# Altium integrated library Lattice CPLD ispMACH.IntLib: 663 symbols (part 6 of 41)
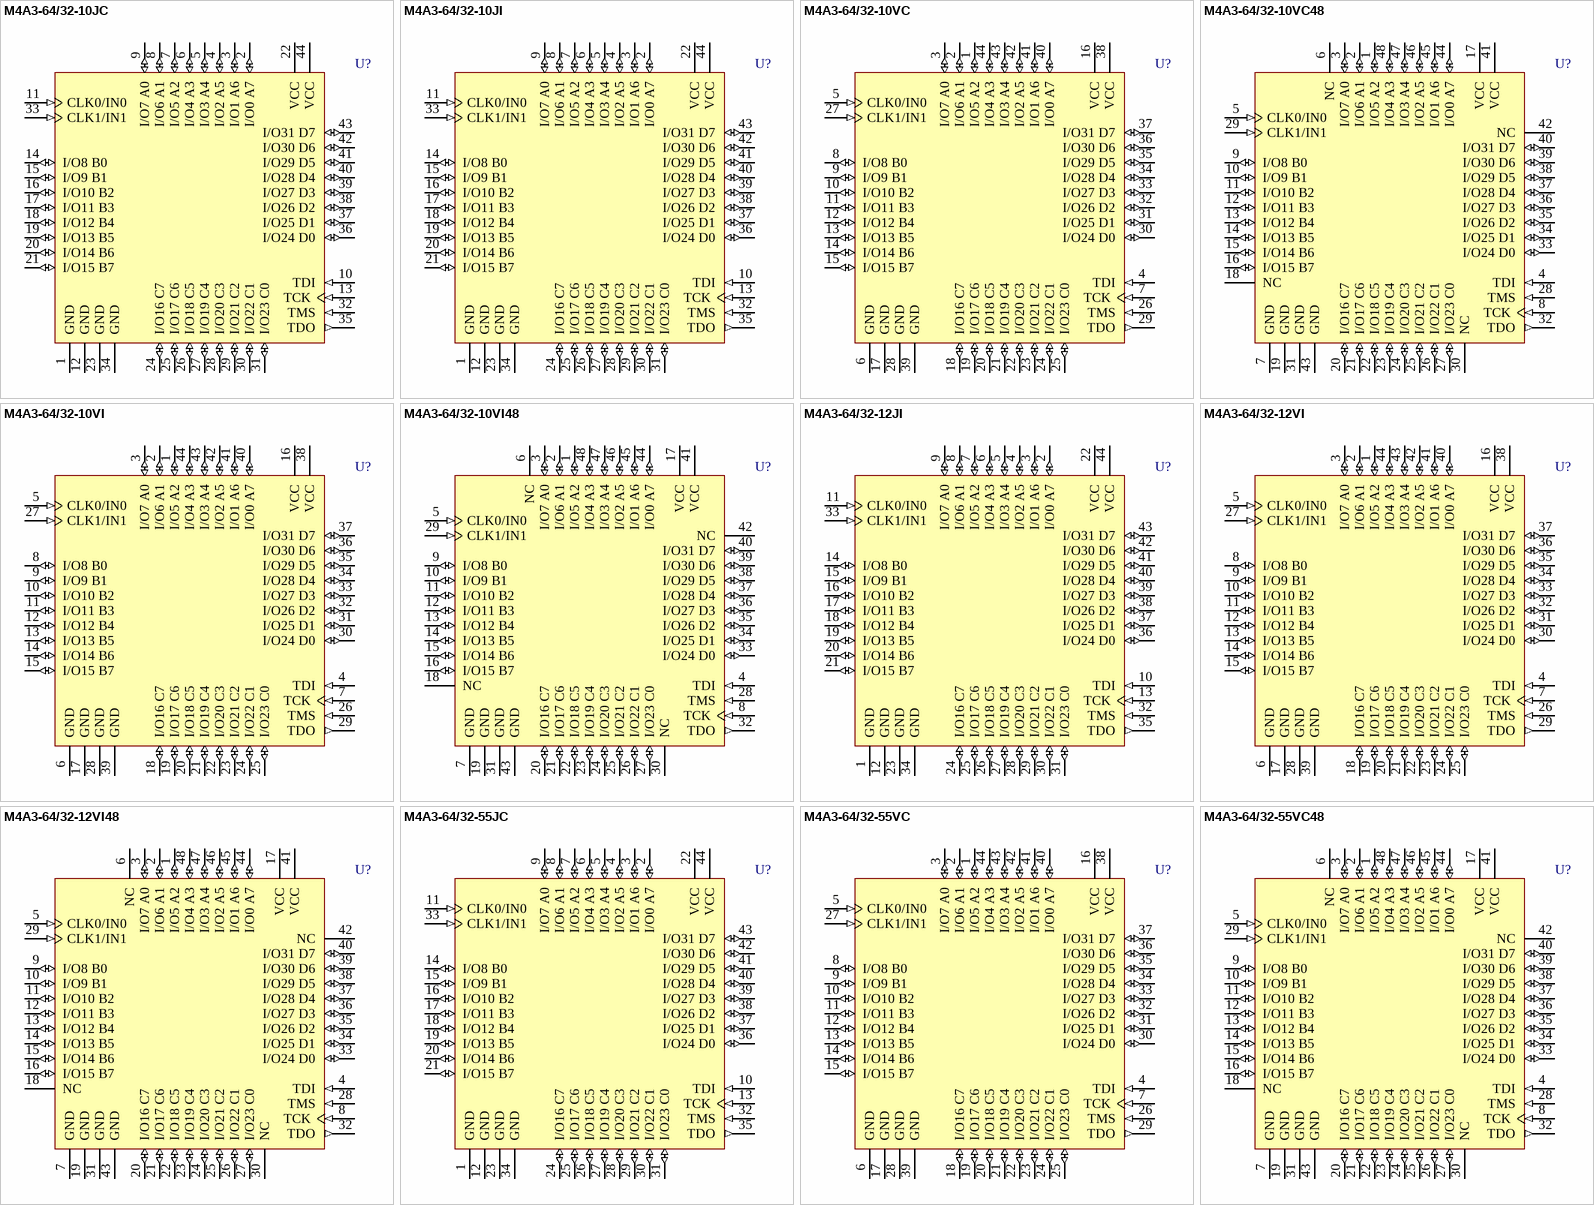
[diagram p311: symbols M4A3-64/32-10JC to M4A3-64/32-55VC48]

## M4A3-64/32-10JC
designator U?
High-Performance EE CMOS In-System Programmable Logic
footprint PLCC44_N (Leaded Chip Carrier, 44-Leads, Body 16.6x16.6mm, Pitch 1.27mm, IPC Medium Density)
footprint PLCC44_L (Leaded Chip Carrier, 44-Leads, Body 16.6x16.6mm, Pitch 1.27mm, IPC High Density)
footprint PLCC44_M (Leaded Chip Carrier, 44-Leads, Body 16.6x16.6mm, Pitch 1.27mm, IPC Low Density)
3D model M4A3-PLCC44 (44-Pin Leaded Chip Carrier 1.27 mm Pitch)
pins: 1 GND (power), 2 I/O0 A7 (io), 3 I/O1 A6 (io), 4 I/O2 A5 (io), 5 I/O3 A4 (io), 6 I/O4 A3 (io), 7 I/O5 A2 (io), 8 I/O6 A1 (io), 9 I/O7 A0 (io), 10 TDI (in), 11 CLK0/IN0 (in), 12 GND (power), 13 TCK (in), 14 I/O8 B0 (io), 15 I/O9 B1 (io), 16 I/O10 B2 (io), 17 I/O11 B3 (io), 18 I/O12 B4 (io), 19 I/O13 B5 (io), 20 I/O14 B6 (io), 21 I/O15 B7 (io), 22 VCC (power), 23 GND (power), 24 I/O16 C7 (io), 25 I/O17 C6 (io), 26 I/O18 C5 (io), 27 I/O19 C4 (io), 28 I/O20 C3 (io), 29 I/O21 C2 (io), 30 I/O22 C1 (io), 31 I/O23 C0 (io), 32 TMS (in), 33 CLK1/IN1 (in), 34 GND (power), 35 TDO (out), 36 I/O24 D0 (io), 37 I/O25 D1 (io), 38 I/O26 D2 (io), 39 I/O27 D3 (io), 40 I/O28 D4 (io), 41 I/O29 D5 (io), 42 I/O30 D6 (io), 43 I/O31 D7 (io), 44 VCC (power)

## M4A3-64/32-10JI
designator U?
High-Performance EE CMOS In-System Programmable Logic
footprint PLCC44_N (Leaded Chip Carrier, 44-Leads, Body 16.6x16.6mm, Pitch 1.27mm, IPC Medium Density)
footprint PLCC44_L (Leaded Chip Carrier, 44-Leads, Body 16.6x16.6mm, Pitch 1.27mm, IPC High Density)
footprint PLCC44_M (Leaded Chip Carrier, 44-Leads, Body 16.6x16.6mm, Pitch 1.27mm, IPC Low Density)
3D model M4A3-PLCC44 (44-Pin Leaded Chip Carrier 1.27 mm Pitch)
pins: 1 GND (power), 2 I/O0 A7 (io), 3 I/O1 A6 (io), 4 I/O2 A5 (io), 5 I/O3 A4 (io), 6 I/O4 A3 (io), 7 I/O5 A2 (io), 8 I/O6 A1 (io), 9 I/O7 A0 (io), 10 TDI (in), 11 CLK0/IN0 (in), 12 GND (power), 13 TCK (in), 14 I/O8 B0 (io), 15 I/O9 B1 (io), 16 I/O10 B2 (io), 17 I/O11 B3 (io), 18 I/O12 B4 (io), 19 I/O13 B5 (io), 20 I/O14 B6 (io), 21 I/O15 B7 (io), 22 VCC (power), 23 GND (power), 24 I/O16 C7 (io), 25 I/O17 C6 (io), 26 I/O18 C5 (io), 27 I/O19 C4 (io), 28 I/O20 C3 (io), 29 I/O21 C2 (io), 30 I/O22 C1 (io), 31 I/O23 C0 (io), 32 TMS (in), 33 CLK1/IN1 (in), 34 GND (power), 35 TDO (out), 36 I/O24 D0 (io), 37 I/O25 D1 (io), 38 I/O26 D2 (io), 39 I/O27 D3 (io), 40 I/O28 D4 (io), 41 I/O29 D5 (io), 42 I/O30 D6 (io), 43 I/O31 D7 (io), 44 VCC (power)

## M4A3-64/32-10VC
designator U?
High-Performance EE CMOS In-System Programmable Logic
footprint TQFP44_N (Thin QFP, 44-Leads, Body 10x10mm, Pitch 0.8mm, IPC Medium Density)
footprint TQFP44_L (Thin QFP, 44-Leads, Body 10x10mm, Pitch 0.8mm, IPC High Density)
footprint TQFP44_M (Thin QFP, 44-Leads, Body 10x10mm, Pitch 0.8mm, IPC Low Density)
3D model M4A3-TQFP44 (44-Pin Thin Quad Flat Pack 0.8 mm Pitch)
pins: 1 I/O5 A2 (io), 2 I/O6 A1 (io), 3 I/O7 A0 (io), 4 TDI (in), 5 CLK0/IN0 (in), 6 GND (power), 7 TCK (in), 8 I/O8 B0 (io), 9 I/O9 B1 (io), 10 I/O10 B2 (io), 11 I/O11 B3 (io), 12 I/O12 B4 (io), 13 I/O13 B5 (io), 14 I/O14 B6 (io), 15 I/O15 B7 (io), 16 VCC (power), 17 GND (power), 18 I/O16 C7 (io), 19 I/O17 C6 (io), 20 I/O18 C5 (io), 21 I/O19 C4 (io), 22 I/O20 C3 (io), 23 I/O21 C2 (io), 24 I/O22 C1 (io), 25 I/O23 C0 (io), 26 TMS (in), 27 CLK1/IN1 (in), 28 GND (power), 29 TDO (out), 30 I/O24 D0 (io), 31 I/O25 D1 (io), 32 I/O26 D2 (io), 33 I/O27 D3 (io), 34 I/O28 D4 (io), 35 I/O29 D5 (io), 36 I/O30 D6 (io), 37 I/O31 D7 (io), 38 VCC (power), 39 GND (power), 40 I/O0 A7 (io), 41 I/O1 A6 (io), 42 I/O2 A5 (io), 43 I/O3 A4 (io), 44 I/O4 A3 (io)

## M4A3-64/32-10VC48
designator U?
High-Performance EE CMOS In-System Programmable Logic
footprint TQFP48_N (Thin QFP, 48-Leads, Body 7x7mm, Pitch 0.5mm, IPC Medium Density)
footprint TQFP48_L (Thin QFP, 48-Leads, Body 7x7mm, Pitch 0.5mm, IPC High Density)
footprint TQFP48_M (Thin QFP, 48-Leads, Body 7x7mm, Pitch 0.5mm, IPC Low Density)
3D model M4A3-TQFP48 (48-Pin Thin Quad Flat Pack 0.5 mm Pitch)
pins: 1 I/O5 A2 (io), 2 I/O6 A1 (io), 3 I/O7 A0 (io), 4 TDI (in), 5 CLK0/IN0 (in), 6 NC, 7 GND (power), 8 TCK (in), 9 I/O8 B0 (io), 10 I/O9 B1 (io), 11 I/O10 B2 (io), 12 I/O11 B3 (io), 13 I/O12 B4 (io), 14 I/O13 B5 (io), 15 I/O14 B6 (io), 16 I/O15 B7 (io), 17 VCC (power), 18 NC, 19 GND (power), 20 I/O16 C7 (io), 21 I/O17 C6 (io), 22 I/O18 C5 (io), 23 I/O19 C4 (io), 24 I/O20 C3 (io), 25 I/O21 C2 (io), 26 I/O22 C1 (io), 27 I/O23 C0 (io), 28 TMS (in), 29 CLK1/IN1 (in), 30 NC, 31 GND (power), 32 TDO (out), 33 I/O24 D0 (io), 34 I/O25 D1 (io), 35 I/O26 D2 (io), 36 I/O27 D3 (io), 37 I/O28 D4 (io), 38 I/O29 D5 (io), 39 I/O30 D6 (io), 40 I/O31 D7 (io), 41 VCC (power), 42 NC, 43 GND (power), 44 I/O0 A7 (io), 45 I/O1 A6 (io), 46 I/O2 A5 (io), 47 I/O3 A4 (io), 48 I/O4 A3 (io)

## M4A3-64/32-10VI
designator U?
High-Performance EE CMOS In-System Programmable Logic
footprint TQFP44_N (Thin QFP, 44-Leads, Body 10x10mm, Pitch 0.8mm, IPC Medium Density)
footprint TQFP44_L (Thin QFP, 44-Leads, Body 10x10mm, Pitch 0.8mm, IPC High Density)
footprint TQFP44_M (Thin QFP, 44-Leads, Body 10x10mm, Pitch 0.8mm, IPC Low Density)
3D model M4A3-TQFP44 (44-Pin Thin Quad Flat Pack 0.8 mm Pitch)
pins: 1 I/O5 A2 (io), 2 I/O6 A1 (io), 3 I/O7 A0 (io), 4 TDI (in), 5 CLK0/IN0 (in), 6 GND (power), 7 TCK (in), 8 I/O8 B0 (io), 9 I/O9 B1 (io), 10 I/O10 B2 (io), 11 I/O11 B3 (io), 12 I/O12 B4 (io), 13 I/O13 B5 (io), 14 I/O14 B6 (io), 15 I/O15 B7 (io), 16 VCC (power), 17 GND (power), 18 I/O16 C7 (io), 19 I/O17 C6 (io), 20 I/O18 C5 (io), 21 I/O19 C4 (io), 22 I/O20 C3 (io), 23 I/O21 C2 (io), 24 I/O22 C1 (io), 25 I/O23 C0 (io), 26 TMS (in), 27 CLK1/IN1 (in), 28 GND (power), 29 TDO (out), 30 I/O24 D0 (io), 31 I/O25 D1 (io), 32 I/O26 D2 (io), 33 I/O27 D3 (io), 34 I/O28 D4 (io), 35 I/O29 D5 (io), 36 I/O30 D6 (io), 37 I/O31 D7 (io), 38 VCC (power), 39 GND (power), 40 I/O0 A7 (io), 41 I/O1 A6 (io), 42 I/O2 A5 (io), 43 I/O3 A4 (io), 44 I/O4 A3 (io)

## M4A3-64/32-10VI48
designator U?
High-Performance EE CMOS In-System Programmable Logic
footprint TQFP48_N (Thin QFP, 48-Leads, Body 7x7mm, Pitch 0.5mm, IPC Medium Density)
footprint TQFP48_L (Thin QFP, 48-Leads, Body 7x7mm, Pitch 0.5mm, IPC High Density)
footprint TQFP48_M (Thin QFP, 48-Leads, Body 7x7mm, Pitch 0.5mm, IPC Low Density)
3D model M4A3-TQFP48 (48-Pin Thin Quad Flat Pack 0.5 mm Pitch)
pins: 1 I/O5 A2 (io), 2 I/O6 A1 (io), 3 I/O7 A0 (io), 4 TDI (in), 5 CLK0/IN0 (in), 6 NC, 7 GND (power), 8 TCK (in), 9 I/O8 B0 (io), 10 I/O9 B1 (io), 11 I/O10 B2 (io), 12 I/O11 B3 (io), 13 I/O12 B4 (io), 14 I/O13 B5 (io), 15 I/O14 B6 (io), 16 I/O15 B7 (io), 17 VCC (power), 18 NC, 19 GND (power), 20 I/O16 C7 (io), 21 I/O17 C6 (io), 22 I/O18 C5 (io), 23 I/O19 C4 (io), 24 I/O20 C3 (io), 25 I/O21 C2 (io), 26 I/O22 C1 (io), 27 I/O23 C0 (io), 28 TMS (in), 29 CLK1/IN1 (in), 30 NC, 31 GND (power), 32 TDO (out), 33 I/O24 D0 (io), 34 I/O25 D1 (io), 35 I/O26 D2 (io), 36 I/O27 D3 (io), 37 I/O28 D4 (io), 38 I/O29 D5 (io), 39 I/O30 D6 (io), 40 I/O31 D7 (io), 41 VCC (power), 42 NC, 43 GND (power), 44 I/O0 A7 (io), 45 I/O1 A6 (io), 46 I/O2 A5 (io), 47 I/O3 A4 (io), 48 I/O4 A3 (io)

## M4A3-64/32-12JI
designator U?
High-Performance EE CMOS In-System Programmable Logic
footprint PLCC44_N (Leaded Chip Carrier, 44-Leads, Body 16.6x16.6mm, Pitch 1.27mm, IPC Medium Density)
footprint PLCC44_L (Leaded Chip Carrier, 44-Leads, Body 16.6x16.6mm, Pitch 1.27mm, IPC High Density)
footprint PLCC44_M (Leaded Chip Carrier, 44-Leads, Body 16.6x16.6mm, Pitch 1.27mm, IPC Low Density)
3D model M4A3-PLCC44 (44-Pin Leaded Chip Carrier 1.27 mm Pitch)
pins: 1 GND (power), 2 I/O0 A7 (io), 3 I/O1 A6 (io), 4 I/O2 A5 (io), 5 I/O3 A4 (io), 6 I/O4 A3 (io), 7 I/O5 A2 (io), 8 I/O6 A1 (io), 9 I/O7 A0 (io), 10 TDI (in), 11 CLK0/IN0 (in), 12 GND (power), 13 TCK (in), 14 I/O8 B0 (io), 15 I/O9 B1 (io), 16 I/O10 B2 (io), 17 I/O11 B3 (io), 18 I/O12 B4 (io), 19 I/O13 B5 (io), 20 I/O14 B6 (io), 21 I/O15 B7 (io), 22 VCC (power), 23 GND (power), 24 I/O16 C7 (io), 25 I/O17 C6 (io), 26 I/O18 C5 (io), 27 I/O19 C4 (io), 28 I/O20 C3 (io), 29 I/O21 C2 (io), 30 I/O22 C1 (io), 31 I/O23 C0 (io), 32 TMS (in), 33 CLK1/IN1 (in), 34 GND (power), 35 TDO (out), 36 I/O24 D0 (io), 37 I/O25 D1 (io), 38 I/O26 D2 (io), 39 I/O27 D3 (io), 40 I/O28 D4 (io), 41 I/O29 D5 (io), 42 I/O30 D6 (io), 43 I/O31 D7 (io), 44 VCC (power)

## M4A3-64/32-12VI
designator U?
High-Performance EE CMOS In-System Programmable Logic
footprint TQFP44_N (Thin QFP, 44-Leads, Body 10x10mm, Pitch 0.8mm, IPC Medium Density)
footprint TQFP44_L (Thin QFP, 44-Leads, Body 10x10mm, Pitch 0.8mm, IPC High Density)
footprint TQFP44_M (Thin QFP, 44-Leads, Body 10x10mm, Pitch 0.8mm, IPC Low Density)
3D model M4A3-TQFP44 (44-Pin Thin Quad Flat Pack 0.8 mm Pitch)
pins: 1 I/O5 A2 (io), 2 I/O6 A1 (io), 3 I/O7 A0 (io), 4 TDI (in), 5 CLK0/IN0 (in), 6 GND (power), 7 TCK (in), 8 I/O8 B0 (io), 9 I/O9 B1 (io), 10 I/O10 B2 (io), 11 I/O11 B3 (io), 12 I/O12 B4 (io), 13 I/O13 B5 (io), 14 I/O14 B6 (io), 15 I/O15 B7 (io), 16 VCC (power), 17 GND (power), 18 I/O16 C7 (io), 19 I/O17 C6 (io), 20 I/O18 C5 (io), 21 I/O19 C4 (io), 22 I/O20 C3 (io), 23 I/O21 C2 (io), 24 I/O22 C1 (io), 25 I/O23 C0 (io), 26 TMS (in), 27 CLK1/IN1 (in), 28 GND (power), 29 TDO (out), 30 I/O24 D0 (io), 31 I/O25 D1 (io), 32 I/O26 D2 (io), 33 I/O27 D3 (io), 34 I/O28 D4 (io), 35 I/O29 D5 (io), 36 I/O30 D6 (io), 37 I/O31 D7 (io), 38 VCC (power), 39 GND (power), 40 I/O0 A7 (io), 41 I/O1 A6 (io), 42 I/O2 A5 (io), 43 I/O3 A4 (io), 44 I/O4 A3 (io)

## M4A3-64/32-12VI48
designator U?
High-Performance EE CMOS In-System Programmable Logic
footprint TQFP48_N (Thin QFP, 48-Leads, Body 7x7mm, Pitch 0.5mm, IPC Medium Density)
footprint TQFP48_L (Thin QFP, 48-Leads, Body 7x7mm, Pitch 0.5mm, IPC High Density)
footprint TQFP48_M (Thin QFP, 48-Leads, Body 7x7mm, Pitch 0.5mm, IPC Low Density)
3D model M4A3-TQFP48 (48-Pin Thin Quad Flat Pack 0.5 mm Pitch)
pins: 1 I/O5 A2 (io), 2 I/O6 A1 (io), 3 I/O7 A0 (io), 4 TDI (in), 5 CLK0/IN0 (in), 6 NC, 7 GND (power), 8 TCK (in), 9 I/O8 B0 (io), 10 I/O9 B1 (io), 11 I/O10 B2 (io), 12 I/O11 B3 (io), 13 I/O12 B4 (io), 14 I/O13 B5 (io), 15 I/O14 B6 (io), 16 I/O15 B7 (io), 17 VCC (power), 18 NC, 19 GND (power), 20 I/O16 C7 (io), 21 I/O17 C6 (io), 22 I/O18 C5 (io), 23 I/O19 C4 (io), 24 I/O20 C3 (io), 25 I/O21 C2 (io), 26 I/O22 C1 (io), 27 I/O23 C0 (io), 28 TMS (in), 29 CLK1/IN1 (in), 30 NC, 31 GND (power), 32 TDO (out), 33 I/O24 D0 (io), 34 I/O25 D1 (io), 35 I/O26 D2 (io), 36 I/O27 D3 (io), 37 I/O28 D4 (io), 38 I/O29 D5 (io), 39 I/O30 D6 (io), 40 I/O31 D7 (io), 41 VCC (power), 42 NC, 43 GND (power), 44 I/O0 A7 (io), 45 I/O1 A6 (io), 46 I/O2 A5 (io), 47 I/O3 A4 (io), 48 I/O4 A3 (io)

## M4A3-64/32-55JC
designator U?
High-Performance EE CMOS In-System Programmable Logic
footprint PLCC44_N (Leaded Chip Carrier, 44-Leads, Body 16.6x16.6mm, Pitch 1.27mm, IPC Medium Density)
footprint PLCC44_L (Leaded Chip Carrier, 44-Leads, Body 16.6x16.6mm, Pitch 1.27mm, IPC High Density)
footprint PLCC44_M (Leaded Chip Carrier, 44-Leads, Body 16.6x16.6mm, Pitch 1.27mm, IPC Low Density)
3D model M4A3-PLCC44 (44-Pin Leaded Chip Carrier 1.27 mm Pitch)
pins: 1 GND (power), 2 I/O0 A7 (io), 3 I/O1 A6 (io), 4 I/O2 A5 (io), 5 I/O3 A4 (io), 6 I/O4 A3 (io), 7 I/O5 A2 (io), 8 I/O6 A1 (io), 9 I/O7 A0 (io), 10 TDI (in), 11 CLK0/IN0 (in), 12 GND (power), 13 TCK (in), 14 I/O8 B0 (io), 15 I/O9 B1 (io), 16 I/O10 B2 (io), 17 I/O11 B3 (io), 18 I/O12 B4 (io), 19 I/O13 B5 (io), 20 I/O14 B6 (io), 21 I/O15 B7 (io), 22 VCC (power), 23 GND (power), 24 I/O16 C7 (io), 25 I/O17 C6 (io), 26 I/O18 C5 (io), 27 I/O19 C4 (io), 28 I/O20 C3 (io), 29 I/O21 C2 (io), 30 I/O22 C1 (io), 31 I/O23 C0 (io), 32 TMS (in), 33 CLK1/IN1 (in), 34 GND (power), 35 TDO (out), 36 I/O24 D0 (io), 37 I/O25 D1 (io), 38 I/O26 D2 (io), 39 I/O27 D3 (io), 40 I/O28 D4 (io), 41 I/O29 D5 (io), 42 I/O30 D6 (io), 43 I/O31 D7 (io), 44 VCC (power)

## M4A3-64/32-55VC
designator U?
High-Performance EE CMOS In-System Programmable Logic
footprint TQFP44_N (Thin QFP, 44-Leads, Body 10x10mm, Pitch 0.8mm, IPC Medium Density)
footprint TQFP44_L (Thin QFP, 44-Leads, Body 10x10mm, Pitch 0.8mm, IPC High Density)
footprint TQFP44_M (Thin QFP, 44-Leads, Body 10x10mm, Pitch 0.8mm, IPC Low Density)
3D model M4A3-TQFP44 (44-Pin Thin Quad Flat Pack 0.8 mm Pitch)
pins: 1 I/O5 A2 (io), 2 I/O6 A1 (io), 3 I/O7 A0 (io), 4 TDI (in), 5 CLK0/IN0 (in), 6 GND (power), 7 TCK (in), 8 I/O8 B0 (io), 9 I/O9 B1 (io), 10 I/O10 B2 (io), 11 I/O11 B3 (io), 12 I/O12 B4 (io), 13 I/O13 B5 (io), 14 I/O14 B6 (io), 15 I/O15 B7 (io), 16 VCC (power), 17 GND (power), 18 I/O16 C7 (io), 19 I/O17 C6 (io), 20 I/O18 C5 (io), 21 I/O19 C4 (io), 22 I/O20 C3 (io), 23 I/O21 C2 (io), 24 I/O22 C1 (io), 25 I/O23 C0 (io), 26 TMS (in), 27 CLK1/IN1 (in), 28 GND (power), 29 TDO (out), 30 I/O24 D0 (io), 31 I/O25 D1 (io), 32 I/O26 D2 (io), 33 I/O27 D3 (io), 34 I/O28 D4 (io), 35 I/O29 D5 (io), 36 I/O30 D6 (io), 37 I/O31 D7 (io), 38 VCC (power), 39 GND (power), 40 I/O0 A7 (io), 41 I/O1 A6 (io), 42 I/O2 A5 (io), 43 I/O3 A4 (io), 44 I/O4 A3 (io)

## M4A3-64/32-55VC48
designator U?
High-Performance EE CMOS In-System Programmable Logic
footprint TQFP48_N (Thin QFP, 48-Leads, Body 7x7mm, Pitch 0.5mm, IPC Medium Density)
footprint TQFP48_L (Thin QFP, 48-Leads, Body 7x7mm, Pitch 0.5mm, IPC High Density)
footprint TQFP48_M (Thin QFP, 48-Leads, Body 7x7mm, Pitch 0.5mm, IPC Low Density)
3D model M4A3-TQFP48 (48-Pin Thin Quad Flat Pack 0.5 mm Pitch)
pins: 1 I/O5 A2 (io), 2 I/O6 A1 (io), 3 I/O7 A0 (io), 4 TDI (in), 5 CLK0/IN0 (in), 6 NC, 7 GND (power), 8 TCK (in), 9 I/O8 B0 (io), 10 I/O9 B1 (io), 11 I/O10 B2 (io), 12 I/O11 B3 (io), 13 I/O12 B4 (io), 14 I/O13 B5 (io), 15 I/O14 B6 (io), 16 I/O15 B7 (io), 17 VCC (power), 18 NC, 19 GND (power), 20 I/O16 C7 (io), 21 I/O17 C6 (io), 22 I/O18 C5 (io), 23 I/O19 C4 (io), 24 I/O20 C3 (io), 25 I/O21 C2 (io), 26 I/O22 C1 (io), 27 I/O23 C0 (io), 28 TMS (in), 29 CLK1/IN1 (in), 30 NC, 31 GND (power), 32 TDO (out), 33 I/O24 D0 (io), 34 I/O25 D1 (io), 35 I/O26 D2 (io), 36 I/O27 D3 (io), 37 I/O28 D4 (io), 38 I/O29 D5 (io), 39 I/O30 D6 (io), 40 I/O31 D7 (io), 41 VCC (power), 42 NC, 43 GND (power), 44 I/O0 A7 (io), 45 I/O1 A6 (io), 46 I/O2 A5 (io), 47 I/O3 A4 (io), 48 I/O4 A3 (io)

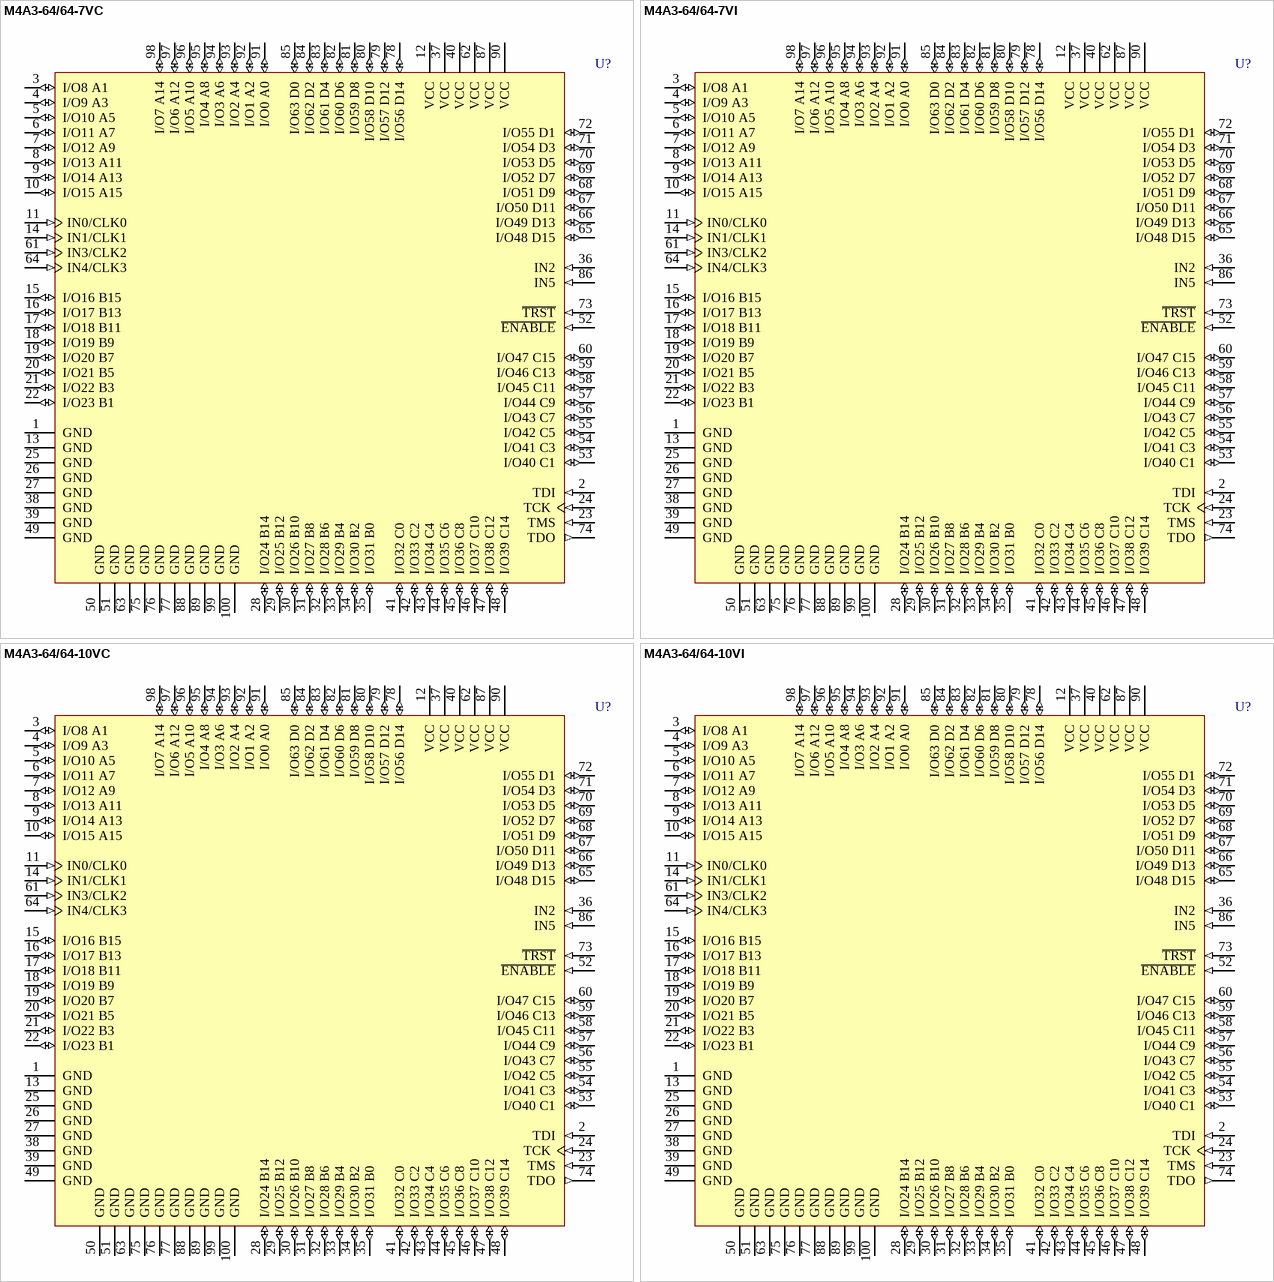
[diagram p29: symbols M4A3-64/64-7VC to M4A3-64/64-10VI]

## M4A3-64/64-7VC
designator U?
High-Performance EE CMOS In-System Programmable Logic
footprint TQFP100_N (Thin QFP, 100-Leads, Body 14x14mm, Pitch 0.5mm, IPC Medium Density)
footprint TQFP100_L (Thin QFP, 100-Leads, Body 14x14mm, Pitch 0.5mm, IPC High Density)
footprint TQFP100_M (Thin QFP, 100-Leads, Body 14x14mm, Pitch 0.5mm, IPC Low Density)
3D model M4A3-TQFP100 (100-Pin Thin Quad Flat Pack (TQFP100))
pins: 1 GND (power), 2 TDI (in), 3 I/O8 A1 (io), 4 I/O9 A3 (io), 5 I/O10 A5 (io), 6 I/O11 A7 (io), 7 I/O12 A9 (io), 8 I/O13 A11 (io), 9 I/O14 A13 (io), 10 I/O15 A15 (io), 11 IN0/CLK0 (in), 12 VCC (power), 13 GND (power), 14 IN1/CLK1 (in), 15 I/O16 B15 (io), 16 I/O17 B13 (io), 17 I/O18 B11 (io), 18 I/O19 B9 (io), 19 I/O20 B7 (io), 20 I/O21 B5 (io), 21 I/O22 B3 (io), 22 I/O23 B1 (io), 23 TMS (in), 24 TCK (in), 25 GND (power), 26 GND (power), 27 GND (power), 28 I/O24 B14 (io), 29 I/O25 B12 (io), 30 I/O26 B10 (io), 31 I/O27 B8 (io), 32 I/O28 B6 (io), 33 I/O29 B4 (io), 34 I/O30 B2 (io), 35 I/O31 B0 (io), 36 IN2 (in), 37 VCC (power), 38 GND (power), 39 GND (power), 40 VCC (power), 41 I/O32 C0 (io), 42 I/O33 C2 (io), 43 I/O34 C4 (io), 44 I/O35 C6 (io), 45 I/O36 C8 (io), 46 I/O37 C10 (io), 47 I/O38 C12 (io), 48 I/O39 C14 (io), 49 GND (power), 50 GND (power), 51 GND (power), 52 ~{ENABLE} (in), 53 I/O40 C1 (io), 54 I/O41 C3 (io), 55 I/O42 C5 (io), 56 I/O43 C7 (io), 57 I/O44 C9 (io), 58 I/O45 C11 (io), 59 I/O46 C13 (io), 60 I/O47 C15 (io), 61 IN3/CLK2 (in), 62 VCC (power), 63 GND (power), 64 IN4/CLK3 (in), 65 I/O48 D15 (io), 66 I/O49 D13 (io), 67 I/O50 D11 (io), 68 I/O51 D9 (io), 69 I/O52 D7 (io), 70 I/O53 D5 (io), 71 I/O54 D3 (io), 72 I/O55 D1 (io), 73 ~{TRST} (in), 74 TDO (out), 75 GND (power), 76 GND (power), 77 GND (power), 78 I/O56 D14 (io), 79 I/O57 D12 (io), 80 I/O58 D10 (io), 81 I/O59 D8 (io), 82 I/O60 D6 (io), 83 I/O61 D4 (io), 84 I/O62 D2 (io), 85 I/O63 D0 (io), 86 IN5 (in), 87 VCC (power), 88 GND (power), 89 GND (power), 90 VCC (power), 91 I/O0 A0 (io), 92 I/O1 A2 (io), 93 I/O2 A4 (io), 94 I/O3 A6 (io), 95 I/O4 A8 (io), 96 I/O5 A10 (io), 97 I/O6 A12 (io), 98 I/O7 A14 (io), 99 GND (power), 100 GND (power)

## M4A3-64/64-7VI
designator U?
High-Performance EE CMOS In-System Programmable Logic
footprint TQFP100_N (Thin QFP, 100-Leads, Body 14x14mm, Pitch 0.5mm, IPC Medium Density)
footprint TQFP100_L (Thin QFP, 100-Leads, Body 14x14mm, Pitch 0.5mm, IPC High Density)
footprint TQFP100_M (Thin QFP, 100-Leads, Body 14x14mm, Pitch 0.5mm, IPC Low Density)
3D model M4A3-TQFP100 (100-Pin Thin Quad Flat Pack (TQFP100))
pins: 1 GND (power), 2 TDI (in), 3 I/O8 A1 (io), 4 I/O9 A3 (io), 5 I/O10 A5 (io), 6 I/O11 A7 (io), 7 I/O12 A9 (io), 8 I/O13 A11 (io), 9 I/O14 A13 (io), 10 I/O15 A15 (io), 11 IN0/CLK0 (in), 12 VCC (power), 13 GND (power), 14 IN1/CLK1 (in), 15 I/O16 B15 (io), 16 I/O17 B13 (io), 17 I/O18 B11 (io), 18 I/O19 B9 (io), 19 I/O20 B7 (io), 20 I/O21 B5 (io), 21 I/O22 B3 (io), 22 I/O23 B1 (io), 23 TMS (in), 24 TCK (in), 25 GND (power), 26 GND (power), 27 GND (power), 28 I/O24 B14 (io), 29 I/O25 B12 (io), 30 I/O26 B10 (io), 31 I/O27 B8 (io), 32 I/O28 B6 (io), 33 I/O29 B4 (io), 34 I/O30 B2 (io), 35 I/O31 B0 (io), 36 IN2 (in), 37 VCC (power), 38 GND (power), 39 GND (power), 40 VCC (power), 41 I/O32 C0 (io), 42 I/O33 C2 (io), 43 I/O34 C4 (io), 44 I/O35 C6 (io), 45 I/O36 C8 (io), 46 I/O37 C10 (io), 47 I/O38 C12 (io), 48 I/O39 C14 (io), 49 GND (power), 50 GND (power), 51 GND (power), 52 ~{ENABLE} (in), 53 I/O40 C1 (io), 54 I/O41 C3 (io), 55 I/O42 C5 (io), 56 I/O43 C7 (io), 57 I/O44 C9 (io), 58 I/O45 C11 (io), 59 I/O46 C13 (io), 60 I/O47 C15 (io), 61 IN3/CLK2 (in), 62 VCC (power), 63 GND (power), 64 IN4/CLK3 (in), 65 I/O48 D15 (io), 66 I/O49 D13 (io), 67 I/O50 D11 (io), 68 I/O51 D9 (io), 69 I/O52 D7 (io), 70 I/O53 D5 (io), 71 I/O54 D3 (io), 72 I/O55 D1 (io), 73 ~{TRST} (in), 74 TDO (out), 75 GND (power), 76 GND (power), 77 GND (power), 78 I/O56 D14 (io), 79 I/O57 D12 (io), 80 I/O58 D10 (io), 81 I/O59 D8 (io), 82 I/O60 D6 (io), 83 I/O61 D4 (io), 84 I/O62 D2 (io), 85 I/O63 D0 (io), 86 IN5 (in), 87 VCC (power), 88 GND (power), 89 GND (power), 90 VCC (power), 91 I/O0 A0 (io), 92 I/O1 A2 (io), 93 I/O2 A4 (io), 94 I/O3 A6 (io), 95 I/O4 A8 (io), 96 I/O5 A10 (io), 97 I/O6 A12 (io), 98 I/O7 A14 (io), 99 GND (power), 100 GND (power)

## M4A3-64/64-10VC
designator U?
High-Performance EE CMOS In-System Programmable Logic
footprint TQFP100_N (Thin QFP, 100-Leads, Body 14x14mm, Pitch 0.5mm, IPC Medium Density)
footprint TQFP100_L (Thin QFP, 100-Leads, Body 14x14mm, Pitch 0.5mm, IPC High Density)
footprint TQFP100_M (Thin QFP, 100-Leads, Body 14x14mm, Pitch 0.5mm, IPC Low Density)
3D model M4A3-TQFP100 (100-Pin Thin Quad Flat Pack (TQFP100))
pins: 1 GND (power), 2 TDI (in), 3 I/O8 A1 (io), 4 I/O9 A3 (io), 5 I/O10 A5 (io), 6 I/O11 A7 (io), 7 I/O12 A9 (io), 8 I/O13 A11 (io), 9 I/O14 A13 (io), 10 I/O15 A15 (io), 11 IN0/CLK0 (in), 12 VCC (power), 13 GND (power), 14 IN1/CLK1 (in), 15 I/O16 B15 (io), 16 I/O17 B13 (io), 17 I/O18 B11 (io), 18 I/O19 B9 (io), 19 I/O20 B7 (io), 20 I/O21 B5 (io), 21 I/O22 B3 (io), 22 I/O23 B1 (io), 23 TMS (in), 24 TCK (in), 25 GND (power), 26 GND (power), 27 GND (power), 28 I/O24 B14 (io), 29 I/O25 B12 (io), 30 I/O26 B10 (io), 31 I/O27 B8 (io), 32 I/O28 B6 (io), 33 I/O29 B4 (io), 34 I/O30 B2 (io), 35 I/O31 B0 (io), 36 IN2 (in), 37 VCC (power), 38 GND (power), 39 GND (power), 40 VCC (power), 41 I/O32 C0 (io), 42 I/O33 C2 (io), 43 I/O34 C4 (io), 44 I/O35 C6 (io), 45 I/O36 C8 (io), 46 I/O37 C10 (io), 47 I/O38 C12 (io), 48 I/O39 C14 (io), 49 GND (power), 50 GND (power), 51 GND (power), 52 ~{ENABLE} (in), 53 I/O40 C1 (io), 54 I/O41 C3 (io), 55 I/O42 C5 (io), 56 I/O43 C7 (io), 57 I/O44 C9 (io), 58 I/O45 C11 (io), 59 I/O46 C13 (io), 60 I/O47 C15 (io), 61 IN3/CLK2 (in), 62 VCC (power), 63 GND (power), 64 IN4/CLK3 (in), 65 I/O48 D15 (io), 66 I/O49 D13 (io), 67 I/O50 D11 (io), 68 I/O51 D9 (io), 69 I/O52 D7 (io), 70 I/O53 D5 (io), 71 I/O54 D3 (io), 72 I/O55 D1 (io), 73 ~{TRST} (in), 74 TDO (out), 75 GND (power), 76 GND (power), 77 GND (power), 78 I/O56 D14 (io), 79 I/O57 D12 (io), 80 I/O58 D10 (io), 81 I/O59 D8 (io), 82 I/O60 D6 (io), 83 I/O61 D4 (io), 84 I/O62 D2 (io), 85 I/O63 D0 (io), 86 IN5 (in), 87 VCC (power), 88 GND (power), 89 GND (power), 90 VCC (power), 91 I/O0 A0 (io), 92 I/O1 A2 (io), 93 I/O2 A4 (io), 94 I/O3 A6 (io), 95 I/O4 A8 (io), 96 I/O5 A10 (io), 97 I/O6 A12 (io), 98 I/O7 A14 (io), 99 GND (power), 100 GND (power)

## M4A3-64/64-10VI
designator U?
High-Performance EE CMOS In-System Programmable Logic
footprint TQFP100_N (Thin QFP, 100-Leads, Body 14x14mm, Pitch 0.5mm, IPC Medium Density)
footprint TQFP100_L (Thin QFP, 100-Leads, Body 14x14mm, Pitch 0.5mm, IPC High Density)
footprint TQFP100_M (Thin QFP, 100-Leads, Body 14x14mm, Pitch 0.5mm, IPC Low Density)
3D model M4A3-TQFP100 (100-Pin Thin Quad Flat Pack (TQFP100))
pins: 1 GND (power), 2 TDI (in), 3 I/O8 A1 (io), 4 I/O9 A3 (io), 5 I/O10 A5 (io), 6 I/O11 A7 (io), 7 I/O12 A9 (io), 8 I/O13 A11 (io), 9 I/O14 A13 (io), 10 I/O15 A15 (io), 11 IN0/CLK0 (in), 12 VCC (power), 13 GND (power), 14 IN1/CLK1 (in), 15 I/O16 B15 (io), 16 I/O17 B13 (io), 17 I/O18 B11 (io), 18 I/O19 B9 (io), 19 I/O20 B7 (io), 20 I/O21 B5 (io), 21 I/O22 B3 (io), 22 I/O23 B1 (io), 23 TMS (in), 24 TCK (in), 25 GND (power), 26 GND (power), 27 GND (power), 28 I/O24 B14 (io), 29 I/O25 B12 (io), 30 I/O26 B10 (io), 31 I/O27 B8 (io), 32 I/O28 B6 (io), 33 I/O29 B4 (io), 34 I/O30 B2 (io), 35 I/O31 B0 (io), 36 IN2 (in), 37 VCC (power), 38 GND (power), 39 GND (power), 40 VCC (power), 41 I/O32 C0 (io), 42 I/O33 C2 (io), 43 I/O34 C4 (io), 44 I/O35 C6 (io), 45 I/O36 C8 (io), 46 I/O37 C10 (io), 47 I/O38 C12 (io), 48 I/O39 C14 (io), 49 GND (power), 50 GND (power), 51 GND (power), 52 ~{ENABLE} (in), 53 I/O40 C1 (io), 54 I/O41 C3 (io), 55 I/O42 C5 (io), 56 I/O43 C7 (io), 57 I/O44 C9 (io), 58 I/O45 C11 (io), 59 I/O46 C13 (io), 60 I/O47 C15 (io), 61 IN3/CLK2 (in), 62 VCC (power), 63 GND (power), 64 IN4/CLK3 (in), 65 I/O48 D15 (io), 66 I/O49 D13 (io), 67 I/O50 D11 (io), 68 I/O51 D9 (io), 69 I/O52 D7 (io), 70 I/O53 D5 (io), 71 I/O54 D3 (io), 72 I/O55 D1 (io), 73 ~{TRST} (in), 74 TDO (out), 75 GND (power), 76 GND (power), 77 GND (power), 78 I/O56 D14 (io), 79 I/O57 D12 (io), 80 I/O58 D10 (io), 81 I/O59 D8 (io), 82 I/O60 D6 (io), 83 I/O61 D4 (io), 84 I/O62 D2 (io), 85 I/O63 D0 (io), 86 IN5 (in), 87 VCC (power), 88 GND (power), 89 GND (power), 90 VCC (power), 91 I/O0 A0 (io), 92 I/O1 A2 (io), 93 I/O2 A4 (io), 94 I/O3 A6 (io), 95 I/O4 A8 (io), 96 I/O5 A10 (io), 97 I/O6 A12 (io), 98 I/O7 A14 (io), 99 GND (power), 100 GND (power)

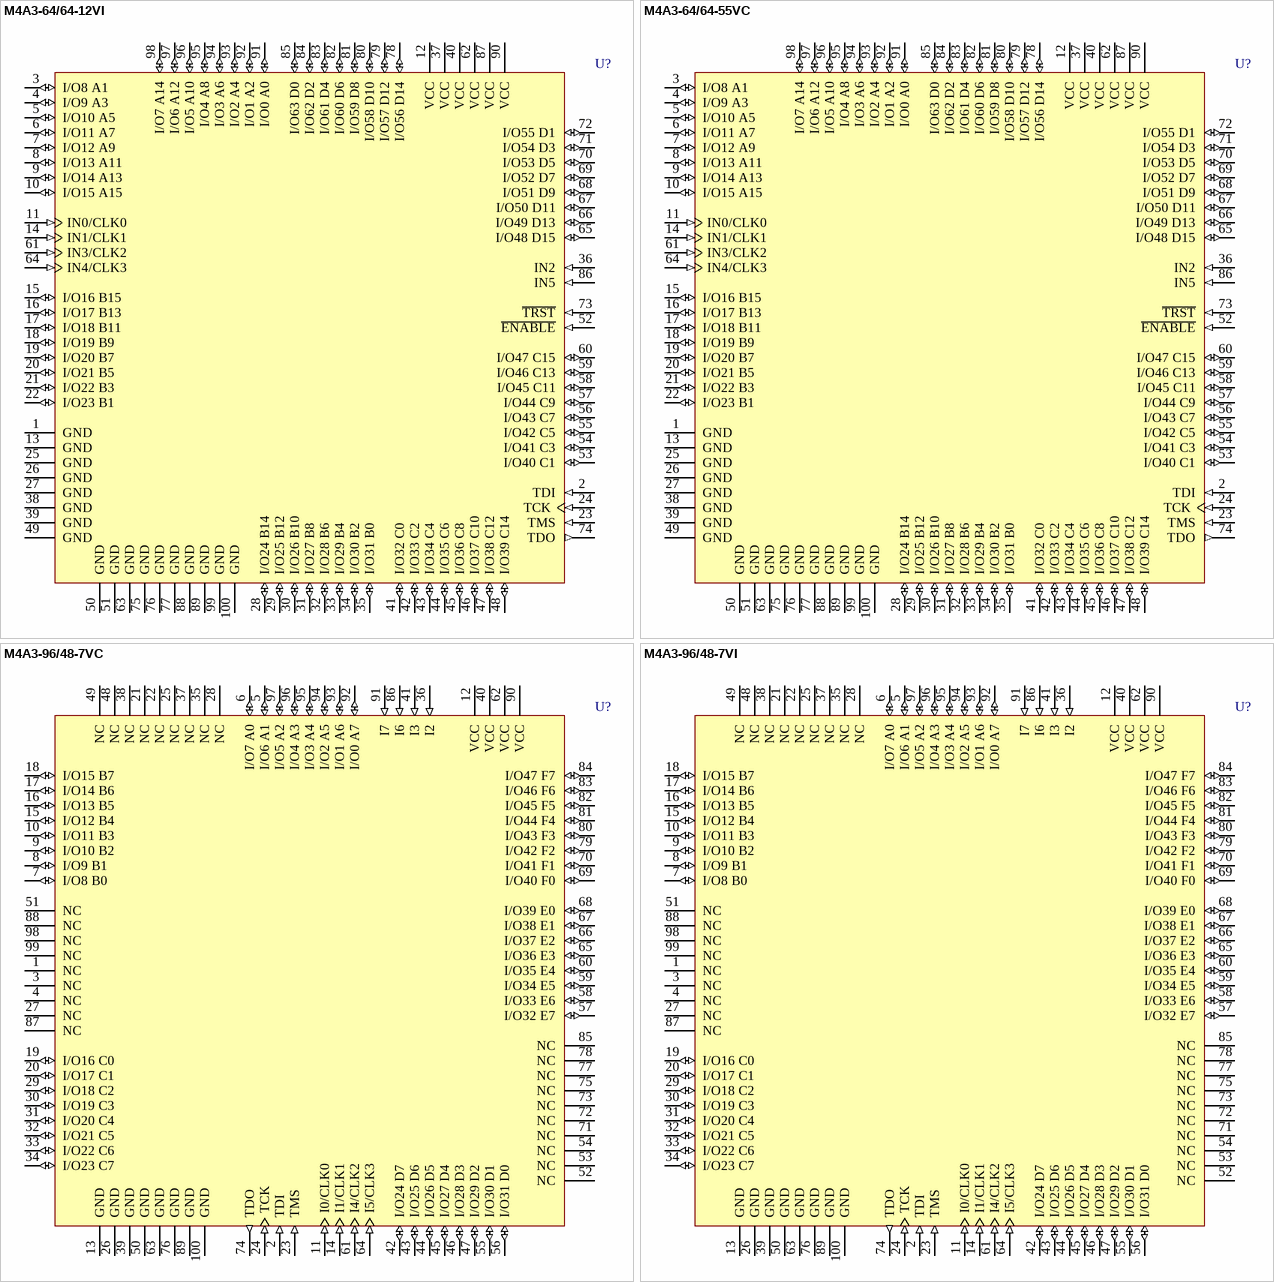
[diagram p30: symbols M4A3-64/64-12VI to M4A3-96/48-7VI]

## M4A3-64/64-12VI
designator U?
High-Performance EE CMOS In-System Programmable Logic
footprint TQFP100_N (Thin QFP, 100-Leads, Body 14x14mm, Pitch 0.5mm, IPC Medium Density)
footprint TQFP100_L (Thin QFP, 100-Leads, Body 14x14mm, Pitch 0.5mm, IPC High Density)
footprint TQFP100_M (Thin QFP, 100-Leads, Body 14x14mm, Pitch 0.5mm, IPC Low Density)
3D model M4A3-TQFP100 (100-Pin Thin Quad Flat Pack (TQFP100))
pins: 1 GND (power), 2 TDI (in), 3 I/O8 A1 (io), 4 I/O9 A3 (io), 5 I/O10 A5 (io), 6 I/O11 A7 (io), 7 I/O12 A9 (io), 8 I/O13 A11 (io), 9 I/O14 A13 (io), 10 I/O15 A15 (io), 11 IN0/CLK0 (in), 12 VCC (power), 13 GND (power), 14 IN1/CLK1 (in), 15 I/O16 B15 (io), 16 I/O17 B13 (io), 17 I/O18 B11 (io), 18 I/O19 B9 (io), 19 I/O20 B7 (io), 20 I/O21 B5 (io), 21 I/O22 B3 (io), 22 I/O23 B1 (io), 23 TMS (in), 24 TCK (in), 25 GND (power), 26 GND (power), 27 GND (power), 28 I/O24 B14 (io), 29 I/O25 B12 (io), 30 I/O26 B10 (io), 31 I/O27 B8 (io), 32 I/O28 B6 (io), 33 I/O29 B4 (io), 34 I/O30 B2 (io), 35 I/O31 B0 (io), 36 IN2 (in), 37 VCC (power), 38 GND (power), 39 GND (power), 40 VCC (power), 41 I/O32 C0 (io), 42 I/O33 C2 (io), 43 I/O34 C4 (io), 44 I/O35 C6 (io), 45 I/O36 C8 (io), 46 I/O37 C10 (io), 47 I/O38 C12 (io), 48 I/O39 C14 (io), 49 GND (power), 50 GND (power), 51 GND (power), 52 ~{ENABLE} (in), 53 I/O40 C1 (io), 54 I/O41 C3 (io), 55 I/O42 C5 (io), 56 I/O43 C7 (io), 57 I/O44 C9 (io), 58 I/O45 C11 (io), 59 I/O46 C13 (io), 60 I/O47 C15 (io), 61 IN3/CLK2 (in), 62 VCC (power), 63 GND (power), 64 IN4/CLK3 (in), 65 I/O48 D15 (io), 66 I/O49 D13 (io), 67 I/O50 D11 (io), 68 I/O51 D9 (io), 69 I/O52 D7 (io), 70 I/O53 D5 (io), 71 I/O54 D3 (io), 72 I/O55 D1 (io), 73 ~{TRST} (in), 74 TDO (out), 75 GND (power), 76 GND (power), 77 GND (power), 78 I/O56 D14 (io), 79 I/O57 D12 (io), 80 I/O58 D10 (io), 81 I/O59 D8 (io), 82 I/O60 D6 (io), 83 I/O61 D4 (io), 84 I/O62 D2 (io), 85 I/O63 D0 (io), 86 IN5 (in), 87 VCC (power), 88 GND (power), 89 GND (power), 90 VCC (power), 91 I/O0 A0 (io), 92 I/O1 A2 (io), 93 I/O2 A4 (io), 94 I/O3 A6 (io), 95 I/O4 A8 (io), 96 I/O5 A10 (io), 97 I/O6 A12 (io), 98 I/O7 A14 (io), 99 GND (power), 100 GND (power)

## M4A3-64/64-55VC
designator U?
High-Performance EE CMOS In-System Programmable Logic
footprint TQFP100_N (Thin QFP, 100-Leads, Body 14x14mm, Pitch 0.5mm, IPC Medium Density)
footprint TQFP100_L (Thin QFP, 100-Leads, Body 14x14mm, Pitch 0.5mm, IPC High Density)
footprint TQFP100_M (Thin QFP, 100-Leads, Body 14x14mm, Pitch 0.5mm, IPC Low Density)
3D model M4A3-TQFP100 (100-Pin Thin Quad Flat Pack (TQFP100))
pins: 1 GND (power), 2 TDI (in), 3 I/O8 A1 (io), 4 I/O9 A3 (io), 5 I/O10 A5 (io), 6 I/O11 A7 (io), 7 I/O12 A9 (io), 8 I/O13 A11 (io), 9 I/O14 A13 (io), 10 I/O15 A15 (io), 11 IN0/CLK0 (in), 12 VCC (power), 13 GND (power), 14 IN1/CLK1 (in), 15 I/O16 B15 (io), 16 I/O17 B13 (io), 17 I/O18 B11 (io), 18 I/O19 B9 (io), 19 I/O20 B7 (io), 20 I/O21 B5 (io), 21 I/O22 B3 (io), 22 I/O23 B1 (io), 23 TMS (in), 24 TCK (in), 25 GND (power), 26 GND (power), 27 GND (power), 28 I/O24 B14 (io), 29 I/O25 B12 (io), 30 I/O26 B10 (io), 31 I/O27 B8 (io), 32 I/O28 B6 (io), 33 I/O29 B4 (io), 34 I/O30 B2 (io), 35 I/O31 B0 (io), 36 IN2 (in), 37 VCC (power), 38 GND (power), 39 GND (power), 40 VCC (power), 41 I/O32 C0 (io), 42 I/O33 C2 (io), 43 I/O34 C4 (io), 44 I/O35 C6 (io), 45 I/O36 C8 (io), 46 I/O37 C10 (io), 47 I/O38 C12 (io), 48 I/O39 C14 (io), 49 GND (power), 50 GND (power), 51 GND (power), 52 ~{ENABLE} (in), 53 I/O40 C1 (io), 54 I/O41 C3 (io), 55 I/O42 C5 (io), 56 I/O43 C7 (io), 57 I/O44 C9 (io), 58 I/O45 C11 (io), 59 I/O46 C13 (io), 60 I/O47 C15 (io), 61 IN3/CLK2 (in), 62 VCC (power), 63 GND (power), 64 IN4/CLK3 (in), 65 I/O48 D15 (io), 66 I/O49 D13 (io), 67 I/O50 D11 (io), 68 I/O51 D9 (io), 69 I/O52 D7 (io), 70 I/O53 D5 (io), 71 I/O54 D3 (io), 72 I/O55 D1 (io), 73 ~{TRST} (in), 74 TDO (out), 75 GND (power), 76 GND (power), 77 GND (power), 78 I/O56 D14 (io), 79 I/O57 D12 (io), 80 I/O58 D10 (io), 81 I/O59 D8 (io), 82 I/O60 D6 (io), 83 I/O61 D4 (io), 84 I/O62 D2 (io), 85 I/O63 D0 (io), 86 IN5 (in), 87 VCC (power), 88 GND (power), 89 GND (power), 90 VCC (power), 91 I/O0 A0 (io), 92 I/O1 A2 (io), 93 I/O2 A4 (io), 94 I/O3 A6 (io), 95 I/O4 A8 (io), 96 I/O5 A10 (io), 97 I/O6 A12 (io), 98 I/O7 A14 (io), 99 GND (power), 100 GND (power)

## M4A3-96/48-7VC
designator U?
High-Performance EE CMOS In-System Programmable Logic
footprint TQFP100_N (Thin QFP, 100-Leads, Body 14x14mm, Pitch 0.5mm, IPC Medium Density)
footprint TQFP100_L (Thin QFP, 100-Leads, Body 14x14mm, Pitch 0.5mm, IPC High Density)
footprint TQFP100_M (Thin QFP, 100-Leads, Body 14x14mm, Pitch 0.5mm, IPC Low Density)
3D model M4A3-TQFP100 (100-Pin Thin Quad Flat Pack (TQFP100))
pins: 1 NC, 2 TDI (in), 3 NC, 4 NC, 5 I/O6 A1 (io), 6 I/O7 A0 (io), 7 I/O8 B0 (io), 8 I/O9 B1 (io), 9 I/O10 B2 (io), 10 I/O11 B3 (io), 11 I0/CLK0 (in), 12 VCC (power), 13 GND (power), 14 I1/CLK1 (in), 15 I/O12 B4 (io), 16 I/O13 B5 (io), 17 I/O14 B6 (io), 18 I/O15 B7 (io), 19 I/O16 C0 (io), 20 I/O17 C1 (io), 21 NC, 22 NC, 23 TMS (in), 24 TCK (in), 25 NC, 26 GND (power), 27 NC, 28 NC, 29 I/O18 C2 (io), 30 I/O19 C3 (io), 31 I/O20 C4 (io), 32 I/O21 C5 (io), 33 I/O22 C6 (io), 34 I/O23 C7 (io), 35 NC, 36 I2 (in), 37 NC, 38 NC, 39 GND (power), 40 VCC (power), 41 I3 (in), 42 I/O24 D7 (io), 43 I/O25 D6 (io), 44 I/O26 D5 (io), 45 I/O27 D4 (io), 46 I/O28 D3 (io), 47 I/O29 D2 (io), 48 NC, 49 NC, 50 GND (power), 51 NC, 52 NC, 53 NC, 54 NC, 55 I/O30 D1 (io), 56 I/O31 D0 (io), 57 I/O32 E7 (io), 58 I/O33 E6 (io), 59 I/O34 E5 (io), 60 I/O35 E4 (io), 61 I4/CLK2 (in), 62 VCC (power), 63 GND (power), 64 I5/CLK3 (in), 65 I/O36 E3 (io), 66 I/O37 E2 (io), 67 I/O38 E1 (io), 68 I/O39 E0 (io), 69 I/O40 F0 (io), 70 I/O41 F1 (io), 71 NC, 72 NC, 73 NC, 74 TDO (out), 75 NC, 76 GND (power), 77 NC, 78 NC, 79 I/O42 F2 (io), 80 I/O43 F3 (io), 81 I/O44 F4 (io), 82 I/O45 F5 (io), 83 I/O46 F6 (io), 84 I/O47 F7 (io), 85 NC, 86 I6 (in), 87 NC, 88 NC, 89 GND (power), 90 VCC (power), 91 I7 (in), 92 I/O0 A7 (io), 93 I/O1 A6 (io), 94 I/O2 A5 (io), 95 I/O3 A4 (io), 96 I/O4 A3 (io), 97 I/O5 A2 (io), 98 NC, 99 NC, 100 GND (power)

## M4A3-96/48-7VI
designator U?
High-Performance EE CMOS In-System Programmable Logic
footprint TQFP100_N (Thin QFP, 100-Leads, Body 14x14mm, Pitch 0.5mm, IPC Medium Density)
footprint TQFP100_L (Thin QFP, 100-Leads, Body 14x14mm, Pitch 0.5mm, IPC High Density)
footprint TQFP100_M (Thin QFP, 100-Leads, Body 14x14mm, Pitch 0.5mm, IPC Low Density)
3D model M4A3-TQFP100 (100-Pin Thin Quad Flat Pack (TQFP100))
pins: 1 NC, 2 TDI (in), 3 NC, 4 NC, 5 I/O6 A1 (io), 6 I/O7 A0 (io), 7 I/O8 B0 (io), 8 I/O9 B1 (io), 9 I/O10 B2 (io), 10 I/O11 B3 (io), 11 I0/CLK0 (in), 12 VCC (power), 13 GND (power), 14 I1/CLK1 (in), 15 I/O12 B4 (io), 16 I/O13 B5 (io), 17 I/O14 B6 (io), 18 I/O15 B7 (io), 19 I/O16 C0 (io), 20 I/O17 C1 (io), 21 NC, 22 NC, 23 TMS (in), 24 TCK (in), 25 NC, 26 GND (power), 27 NC, 28 NC, 29 I/O18 C2 (io), 30 I/O19 C3 (io), 31 I/O20 C4 (io), 32 I/O21 C5 (io), 33 I/O22 C6 (io), 34 I/O23 C7 (io), 35 NC, 36 I2 (in), 37 NC, 38 NC, 39 GND (power), 40 VCC (power), 41 I3 (in), 42 I/O24 D7 (io), 43 I/O25 D6 (io), 44 I/O26 D5 (io), 45 I/O27 D4 (io), 46 I/O28 D3 (io), 47 I/O29 D2 (io), 48 NC, 49 NC, 50 GND (power), 51 NC, 52 NC, 53 NC, 54 NC, 55 I/O30 D1 (io), 56 I/O31 D0 (io), 57 I/O32 E7 (io), 58 I/O33 E6 (io), 59 I/O34 E5 (io), 60 I/O35 E4 (io), 61 I4/CLK2 (in), 62 VCC (power), 63 GND (power), 64 I5/CLK3 (in), 65 I/O36 E3 (io), 66 I/O37 E2 (io), 67 I/O38 E1 (io), 68 I/O39 E0 (io), 69 I/O40 F0 (io), 70 I/O41 F1 (io), 71 NC, 72 NC, 73 NC, 74 TDO (out), 75 NC, 76 GND (power), 77 NC, 78 NC, 79 I/O42 F2 (io), 80 I/O43 F3 (io), 81 I/O44 F4 (io), 82 I/O45 F5 (io), 83 I/O46 F6 (io), 84 I/O47 F7 (io), 85 NC, 86 I6 (in), 87 NC, 88 NC, 89 GND (power), 90 VCC (power), 91 I7 (in), 92 I/O0 A7 (io), 93 I/O1 A6 (io), 94 I/O2 A5 (io), 95 I/O3 A4 (io), 96 I/O4 A3 (io), 97 I/O5 A2 (io), 98 NC, 99 NC, 100 GND (power)

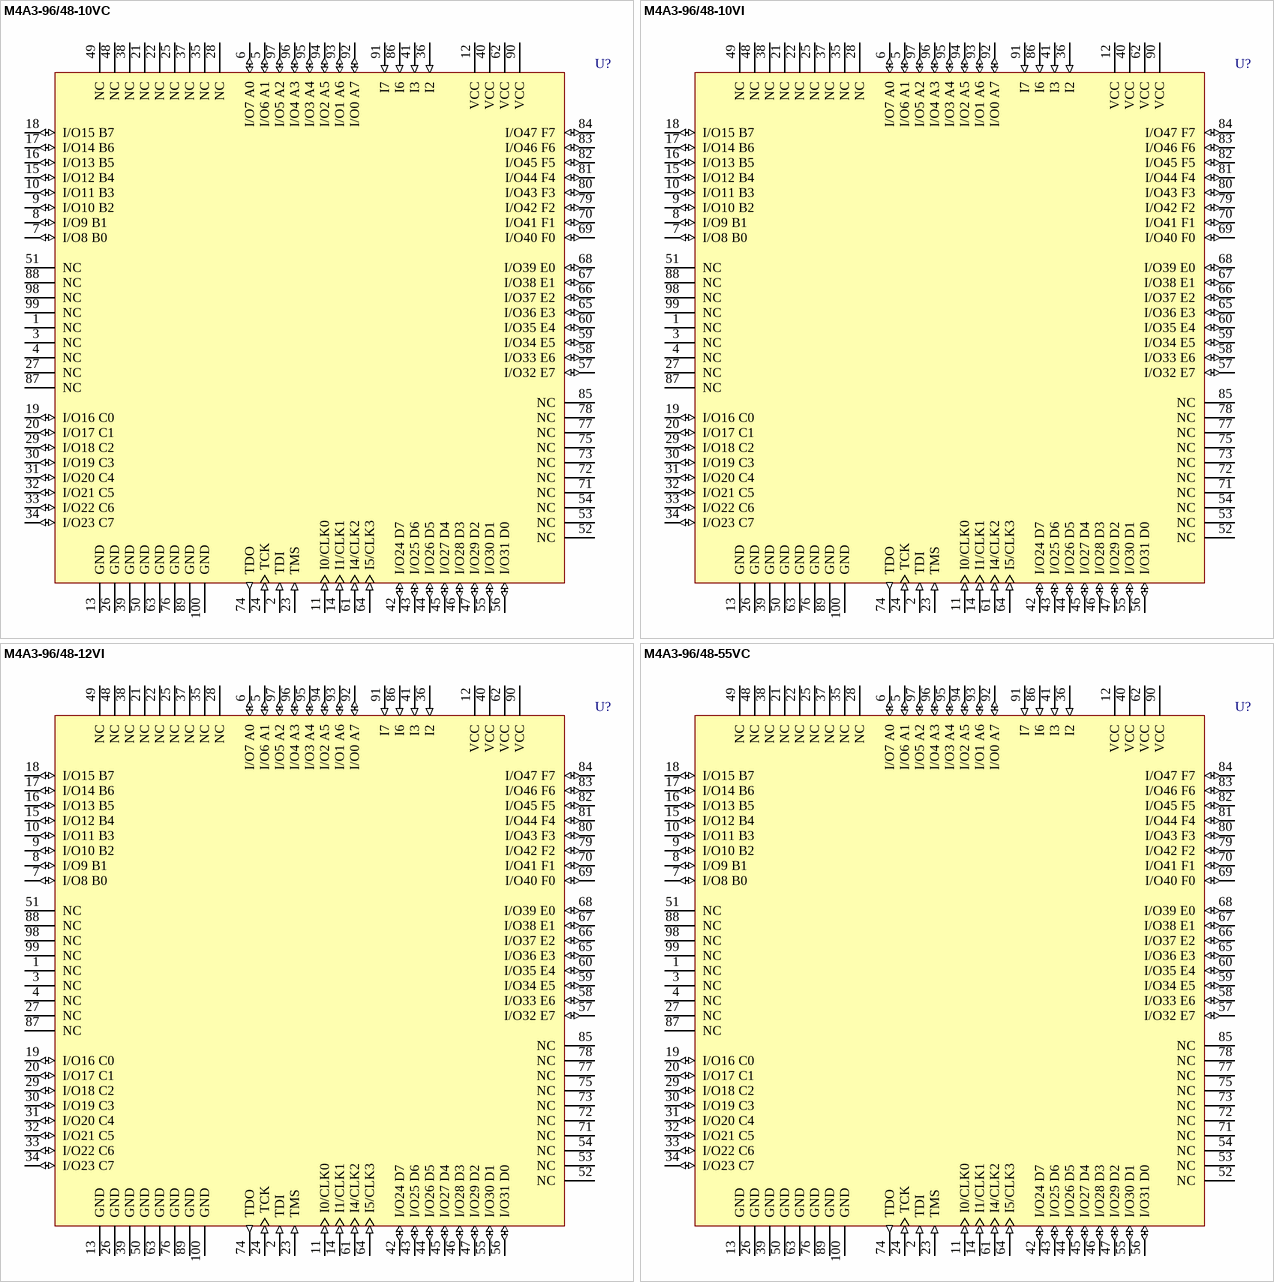
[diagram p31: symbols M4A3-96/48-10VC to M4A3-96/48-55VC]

## M4A3-96/48-10VC
designator U?
High-Performance EE CMOS In-System Programmable Logic
footprint TQFP100_N (Thin QFP, 100-Leads, Body 14x14mm, Pitch 0.5mm, IPC Medium Density)
footprint TQFP100_L (Thin QFP, 100-Leads, Body 14x14mm, Pitch 0.5mm, IPC High Density)
footprint TQFP100_M (Thin QFP, 100-Leads, Body 14x14mm, Pitch 0.5mm, IPC Low Density)
3D model M4A3-TQFP100 (100-Pin Thin Quad Flat Pack (TQFP100))
pins: 1 NC, 2 TDI (in), 3 NC, 4 NC, 5 I/O6 A1 (io), 6 I/O7 A0 (io), 7 I/O8 B0 (io), 8 I/O9 B1 (io), 9 I/O10 B2 (io), 10 I/O11 B3 (io), 11 I0/CLK0 (in), 12 VCC (power), 13 GND (power), 14 I1/CLK1 (in), 15 I/O12 B4 (io), 16 I/O13 B5 (io), 17 I/O14 B6 (io), 18 I/O15 B7 (io), 19 I/O16 C0 (io), 20 I/O17 C1 (io), 21 NC, 22 NC, 23 TMS (in), 24 TCK (in), 25 NC, 26 GND (power), 27 NC, 28 NC, 29 I/O18 C2 (io), 30 I/O19 C3 (io), 31 I/O20 C4 (io), 32 I/O21 C5 (io), 33 I/O22 C6 (io), 34 I/O23 C7 (io), 35 NC, 36 I2 (in), 37 NC, 38 NC, 39 GND (power), 40 VCC (power), 41 I3 (in), 42 I/O24 D7 (io), 43 I/O25 D6 (io), 44 I/O26 D5 (io), 45 I/O27 D4 (io), 46 I/O28 D3 (io), 47 I/O29 D2 (io), 48 NC, 49 NC, 50 GND (power), 51 NC, 52 NC, 53 NC, 54 NC, 55 I/O30 D1 (io), 56 I/O31 D0 (io), 57 I/O32 E7 (io), 58 I/O33 E6 (io), 59 I/O34 E5 (io), 60 I/O35 E4 (io), 61 I4/CLK2 (in), 62 VCC (power), 63 GND (power), 64 I5/CLK3 (in), 65 I/O36 E3 (io), 66 I/O37 E2 (io), 67 I/O38 E1 (io), 68 I/O39 E0 (io), 69 I/O40 F0 (io), 70 I/O41 F1 (io), 71 NC, 72 NC, 73 NC, 74 TDO (out), 75 NC, 76 GND (power), 77 NC, 78 NC, 79 I/O42 F2 (io), 80 I/O43 F3 (io), 81 I/O44 F4 (io), 82 I/O45 F5 (io), 83 I/O46 F6 (io), 84 I/O47 F7 (io), 85 NC, 86 I6 (in), 87 NC, 88 NC, 89 GND (power), 90 VCC (power), 91 I7 (in), 92 I/O0 A7 (io), 93 I/O1 A6 (io), 94 I/O2 A5 (io), 95 I/O3 A4 (io), 96 I/O4 A3 (io), 97 I/O5 A2 (io), 98 NC, 99 NC, 100 GND (power)

## M4A3-96/48-10VI
designator U?
High-Performance EE CMOS In-System Programmable Logic
footprint TQFP100_N (Thin QFP, 100-Leads, Body 14x14mm, Pitch 0.5mm, IPC Medium Density)
footprint TQFP100_L (Thin QFP, 100-Leads, Body 14x14mm, Pitch 0.5mm, IPC High Density)
footprint TQFP100_M (Thin QFP, 100-Leads, Body 14x14mm, Pitch 0.5mm, IPC Low Density)
3D model M4A3-TQFP100 (100-Pin Thin Quad Flat Pack (TQFP100))
pins: 1 NC, 2 TDI (in), 3 NC, 4 NC, 5 I/O6 A1 (io), 6 I/O7 A0 (io), 7 I/O8 B0 (io), 8 I/O9 B1 (io), 9 I/O10 B2 (io), 10 I/O11 B3 (io), 11 I0/CLK0 (in), 12 VCC (power), 13 GND (power), 14 I1/CLK1 (in), 15 I/O12 B4 (io), 16 I/O13 B5 (io), 17 I/O14 B6 (io), 18 I/O15 B7 (io), 19 I/O16 C0 (io), 20 I/O17 C1 (io), 21 NC, 22 NC, 23 TMS (in), 24 TCK (in), 25 NC, 26 GND (power), 27 NC, 28 NC, 29 I/O18 C2 (io), 30 I/O19 C3 (io), 31 I/O20 C4 (io), 32 I/O21 C5 (io), 33 I/O22 C6 (io), 34 I/O23 C7 (io), 35 NC, 36 I2 (in), 37 NC, 38 NC, 39 GND (power), 40 VCC (power), 41 I3 (in), 42 I/O24 D7 (io), 43 I/O25 D6 (io), 44 I/O26 D5 (io), 45 I/O27 D4 (io), 46 I/O28 D3 (io), 47 I/O29 D2 (io), 48 NC, 49 NC, 50 GND (power), 51 NC, 52 NC, 53 NC, 54 NC, 55 I/O30 D1 (io), 56 I/O31 D0 (io), 57 I/O32 E7 (io), 58 I/O33 E6 (io), 59 I/O34 E5 (io), 60 I/O35 E4 (io), 61 I4/CLK2 (in), 62 VCC (power), 63 GND (power), 64 I5/CLK3 (in), 65 I/O36 E3 (io), 66 I/O37 E2 (io), 67 I/O38 E1 (io), 68 I/O39 E0 (io), 69 I/O40 F0 (io), 70 I/O41 F1 (io), 71 NC, 72 NC, 73 NC, 74 TDO (out), 75 NC, 76 GND (power), 77 NC, 78 NC, 79 I/O42 F2 (io), 80 I/O43 F3 (io), 81 I/O44 F4 (io), 82 I/O45 F5 (io), 83 I/O46 F6 (io), 84 I/O47 F7 (io), 85 NC, 86 I6 (in), 87 NC, 88 NC, 89 GND (power), 90 VCC (power), 91 I7 (in), 92 I/O0 A7 (io), 93 I/O1 A6 (io), 94 I/O2 A5 (io), 95 I/O3 A4 (io), 96 I/O4 A3 (io), 97 I/O5 A2 (io), 98 NC, 99 NC, 100 GND (power)

## M4A3-96/48-12VI
designator U?
High-Performance EE CMOS In-System Programmable Logic
footprint TQFP100_N (Thin QFP, 100-Leads, Body 14x14mm, Pitch 0.5mm, IPC Medium Density)
footprint TQFP100_L (Thin QFP, 100-Leads, Body 14x14mm, Pitch 0.5mm, IPC High Density)
footprint TQFP100_M (Thin QFP, 100-Leads, Body 14x14mm, Pitch 0.5mm, IPC Low Density)
3D model M4A3-TQFP100 (100-Pin Thin Quad Flat Pack (TQFP100))
pins: 1 NC, 2 TDI (in), 3 NC, 4 NC, 5 I/O6 A1 (io), 6 I/O7 A0 (io), 7 I/O8 B0 (io), 8 I/O9 B1 (io), 9 I/O10 B2 (io), 10 I/O11 B3 (io), 11 I0/CLK0 (in), 12 VCC (power), 13 GND (power), 14 I1/CLK1 (in), 15 I/O12 B4 (io), 16 I/O13 B5 (io), 17 I/O14 B6 (io), 18 I/O15 B7 (io), 19 I/O16 C0 (io), 20 I/O17 C1 (io), 21 NC, 22 NC, 23 TMS (in), 24 TCK (in), 25 NC, 26 GND (power), 27 NC, 28 NC, 29 I/O18 C2 (io), 30 I/O19 C3 (io), 31 I/O20 C4 (io), 32 I/O21 C5 (io), 33 I/O22 C6 (io), 34 I/O23 C7 (io), 35 NC, 36 I2 (in), 37 NC, 38 NC, 39 GND (power), 40 VCC (power), 41 I3 (in), 42 I/O24 D7 (io), 43 I/O25 D6 (io), 44 I/O26 D5 (io), 45 I/O27 D4 (io), 46 I/O28 D3 (io), 47 I/O29 D2 (io), 48 NC, 49 NC, 50 GND (power), 51 NC, 52 NC, 53 NC, 54 NC, 55 I/O30 D1 (io), 56 I/O31 D0 (io), 57 I/O32 E7 (io), 58 I/O33 E6 (io), 59 I/O34 E5 (io), 60 I/O35 E4 (io), 61 I4/CLK2 (in), 62 VCC (power), 63 GND (power), 64 I5/CLK3 (in), 65 I/O36 E3 (io), 66 I/O37 E2 (io), 67 I/O38 E1 (io), 68 I/O39 E0 (io), 69 I/O40 F0 (io), 70 I/O41 F1 (io), 71 NC, 72 NC, 73 NC, 74 TDO (out), 75 NC, 76 GND (power), 77 NC, 78 NC, 79 I/O42 F2 (io), 80 I/O43 F3 (io), 81 I/O44 F4 (io), 82 I/O45 F5 (io), 83 I/O46 F6 (io), 84 I/O47 F7 (io), 85 NC, 86 I6 (in), 87 NC, 88 NC, 89 GND (power), 90 VCC (power), 91 I7 (in), 92 I/O0 A7 (io), 93 I/O1 A6 (io), 94 I/O2 A5 (io), 95 I/O3 A4 (io), 96 I/O4 A3 (io), 97 I/O5 A2 (io), 98 NC, 99 NC, 100 GND (power)

## M4A3-96/48-55VC
designator U?
High-Performance EE CMOS In-System Programmable Logic
footprint TQFP100_N (Thin QFP, 100-Leads, Body 14x14mm, Pitch 0.5mm, IPC Medium Density)
footprint TQFP100_L (Thin QFP, 100-Leads, Body 14x14mm, Pitch 0.5mm, IPC High Density)
footprint TQFP100_M (Thin QFP, 100-Leads, Body 14x14mm, Pitch 0.5mm, IPC Low Density)
3D model M4A3-TQFP100 (100-Pin Thin Quad Flat Pack (TQFP100))
pins: 1 NC, 2 TDI (in), 3 NC, 4 NC, 5 I/O6 A1 (io), 6 I/O7 A0 (io), 7 I/O8 B0 (io), 8 I/O9 B1 (io), 9 I/O10 B2 (io), 10 I/O11 B3 (io), 11 I0/CLK0 (in), 12 VCC (power), 13 GND (power), 14 I1/CLK1 (in), 15 I/O12 B4 (io), 16 I/O13 B5 (io), 17 I/O14 B6 (io), 18 I/O15 B7 (io), 19 I/O16 C0 (io), 20 I/O17 C1 (io), 21 NC, 22 NC, 23 TMS (in), 24 TCK (in), 25 NC, 26 GND (power), 27 NC, 28 NC, 29 I/O18 C2 (io), 30 I/O19 C3 (io), 31 I/O20 C4 (io), 32 I/O21 C5 (io), 33 I/O22 C6 (io), 34 I/O23 C7 (io), 35 NC, 36 I2 (in), 37 NC, 38 NC, 39 GND (power), 40 VCC (power), 41 I3 (in), 42 I/O24 D7 (io), 43 I/O25 D6 (io), 44 I/O26 D5 (io), 45 I/O27 D4 (io), 46 I/O28 D3 (io), 47 I/O29 D2 (io), 48 NC, 49 NC, 50 GND (power), 51 NC, 52 NC, 53 NC, 54 NC, 55 I/O30 D1 (io), 56 I/O31 D0 (io), 57 I/O32 E7 (io), 58 I/O33 E6 (io), 59 I/O34 E5 (io), 60 I/O35 E4 (io), 61 I4/CLK2 (in), 62 VCC (power), 63 GND (power), 64 I5/CLK3 (in), 65 I/O36 E3 (io), 66 I/O37 E2 (io), 67 I/O38 E1 (io), 68 I/O39 E0 (io), 69 I/O40 F0 (io), 70 I/O41 F1 (io), 71 NC, 72 NC, 73 NC, 74 TDO (out), 75 NC, 76 GND (power), 77 NC, 78 NC, 79 I/O42 F2 (io), 80 I/O43 F3 (io), 81 I/O44 F4 (io), 82 I/O45 F5 (io), 83 I/O46 F6 (io), 84 I/O47 F7 (io), 85 NC, 86 I6 (in), 87 NC, 88 NC, 89 GND (power), 90 VCC (power), 91 I7 (in), 92 I/O0 A7 (io), 93 I/O1 A6 (io), 94 I/O2 A5 (io), 95 I/O3 A4 (io), 96 I/O4 A3 (io), 97 I/O5 A2 (io), 98 NC, 99 NC, 100 GND (power)

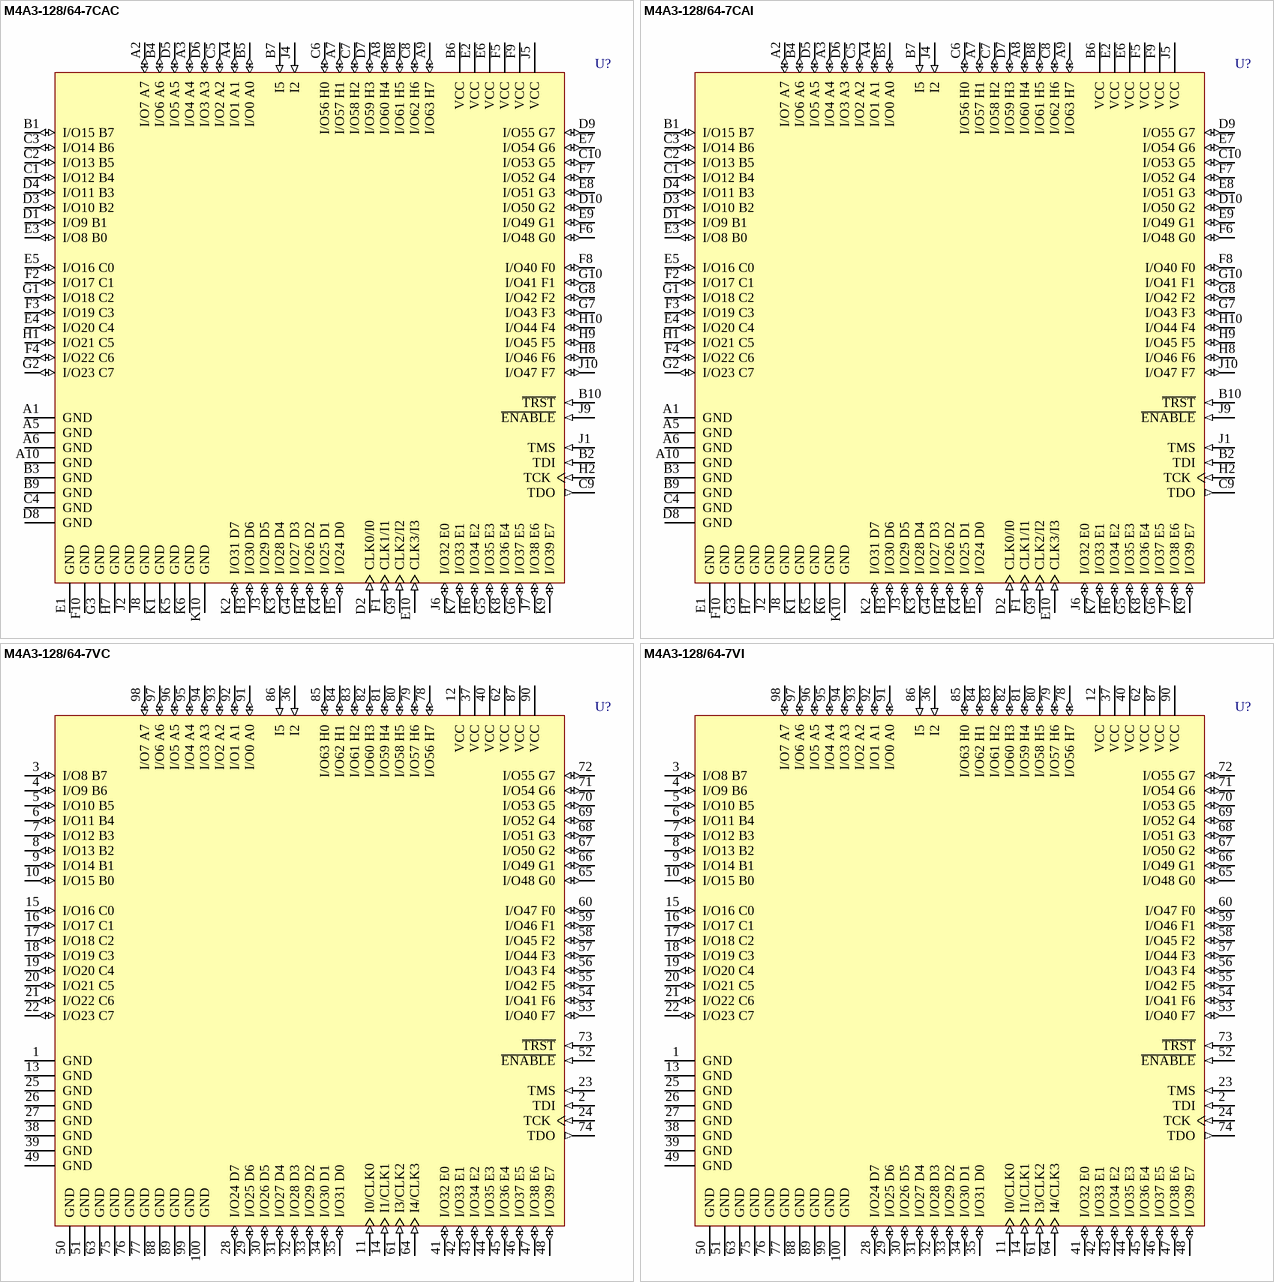
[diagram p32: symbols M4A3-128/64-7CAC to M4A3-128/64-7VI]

## M4A3-128/64-7CAC
designator U?
High-Performance EE CMOS In-System Programmable Logic
footprint caBGA100 (BGA, 100-Leads, Body 10x10mm, Pitch 0.8mm)
3D model M4A3-CaBGA100 (100-Ball Chip Array Ball Grid Array (caBGA100))
pins: A1 GND (power), A2 I/O7 A7 (io), A3 I/O4 A4 (io), A4 I/O1 A1 (io), A5 GND (power), A6 GND (power), A7 I/O57 H1 (io), A8 I/O60 H4 (io), A9 I/O63 H7 (io), A10 GND (power), B1 I/O15 B7 (io), B2 TDI (in), B3 GND (power), B4 I/O6 A6 (io), B5 I/O0 A0 (io), B6 VCC (power), B7 I5 (in), B8 I/O61 H5 (io), B9 GND (power), B10 ~{TRST} (in), C1 I/O12 B4 (io), C2 I/O13 B5 (io), C3 I/O14 B6 (io), C4 GND (power), C5 I/O2 A2 (io), C6 I/O56 H0 (io), C7 I/O58 H2 (io), C8 I/O62 H6 (io), C9 TDO (out), C10 I/O53 G5 (io), D1 I/O9 B1 (io), D2 CLK0/I0 (in), D3 I/O10 B2 (io), D4 I/O11 B3 (io), D5 I/O5 A5 (io), D6 I/O3 A3 (io), D7 I/O59 H3 (io), D8 GND (power), D9 I/O55 G7 (io), D10 I/O50 G2 (io), E1 GND (power), E2 VCC (power), E3 I/O8 B0 (io), E4 I/O20 C4 (io), E5 I/O16 C0 (io), E6 VCC (power), E7 I/O54 G6 (io), E8 I/O51 G3 (io), E9 I/O49 G1 (io), E10 CLK3/I3 (in), F1 CLK1/I1 (in), F2 I/O17 C1 (io), F3 I/O19 C3 (io), F4 I/O22 C6 (io), F5 VCC (power), F6 I/O48 G0 (io), F7 I/O52 G4 (io), F8 I/O40 F0 (io), F9 VCC (power), F10 GND (power), G1 I/O18 C2 (io), G2 I/O23 C7 (io), G3 GND (power), G4 I/O27 D3 (io), G5 I/O35 E3 (io), G6 I/O37 E5 (io), G7 I/O43 F3 (io), G8 I/O42 F2 (io), G9 CLK2/I2 (in), G10 I/O41 F1 (io), H1 I/O21 C5 (io), H2 TCK (in), H3 I/O30 D6 (io), H4 I/O26 D2 (io), H5 I/O24 D0 (io), H6 I/O34 E2 (io), H7 GND (power), H8 I/O46 F6 (io), H9 I/O45 F5 (io), H10 I/O44 F4 (io), J1 TMS (in), J2 GND (power), J3 I/O29 D5 (io), J4 I2 (in), J5 VCC (power), J6 I/O32 E0 (io), J7 I/O38 E6 (io), J8 GND (power), J9 ~{ENABLE} (in), J10 I/O47 F7 (io), K1 GND (power), K2 I/O31 D7 (io), K3 I/O28 D4 (io), K4 I/O25 D1 (io), K5 GND (power), K6 GND (power), K7 I/O33 E1 (io), K8 I/O36 E4 (io), K9 I/O39 E7 (io), K10 GND (power)

## M4A3-128/64-7CAI
designator U?
High-Performance EE CMOS In-System Programmable Logic
footprint caBGA100 (BGA, 100-Leads, Body 10x10mm, Pitch 0.8mm)
3D model M4A3-CaBGA100 (100-Ball Chip Array Ball Grid Array (caBGA100))
pins: A1 GND (power), A2 I/O7 A7 (io), A3 I/O4 A4 (io), A4 I/O1 A1 (io), A5 GND (power), A6 GND (power), A7 I/O57 H1 (io), A8 I/O60 H4 (io), A9 I/O63 H7 (io), A10 GND (power), B1 I/O15 B7 (io), B2 TDI (in), B3 GND (power), B4 I/O6 A6 (io), B5 I/O0 A0 (io), B6 VCC (power), B7 I5 (in), B8 I/O61 H5 (io), B9 GND (power), B10 ~{TRST} (in), C1 I/O12 B4 (io), C2 I/O13 B5 (io), C3 I/O14 B6 (io), C4 GND (power), C5 I/O2 A2 (io), C6 I/O56 H0 (io), C7 I/O58 H2 (io), C8 I/O62 H6 (io), C9 TDO (out), C10 I/O53 G5 (io), D1 I/O9 B1 (io), D2 CLK0/I0 (in), D3 I/O10 B2 (io), D4 I/O11 B3 (io), D5 I/O5 A5 (io), D6 I/O3 A3 (io), D7 I/O59 H3 (io), D8 GND (power), D9 I/O55 G7 (io), D10 I/O50 G2 (io), E1 GND (power), E2 VCC (power), E3 I/O8 B0 (io), E4 I/O20 C4 (io), E5 I/O16 C0 (io), E6 VCC (power), E7 I/O54 G6 (io), E8 I/O51 G3 (io), E9 I/O49 G1 (io), E10 CLK3/I3 (in), F1 CLK1/I1 (in), F2 I/O17 C1 (io), F3 I/O19 C3 (io), F4 I/O22 C6 (io), F5 VCC (power), F6 I/O48 G0 (io), F7 I/O52 G4 (io), F8 I/O40 F0 (io), F9 VCC (power), F10 GND (power), G1 I/O18 C2 (io), G2 I/O23 C7 (io), G3 GND (power), G4 I/O27 D3 (io), G5 I/O35 E3 (io), G6 I/O37 E5 (io), G7 I/O43 F3 (io), G8 I/O42 F2 (io), G9 CLK2/I2 (in), G10 I/O41 F1 (io), H1 I/O21 C5 (io), H2 TCK (in), H3 I/O30 D6 (io), H4 I/O26 D2 (io), H5 I/O24 D0 (io), H6 I/O34 E2 (io), H7 GND (power), H8 I/O46 F6 (io), H9 I/O45 F5 (io), H10 I/O44 F4 (io), J1 TMS (in), J2 GND (power), J3 I/O29 D5 (io), J4 I2 (in), J5 VCC (power), J6 I/O32 E0 (io), J7 I/O38 E6 (io), J8 GND (power), J9 ~{ENABLE} (in), J10 I/O47 F7 (io), K1 GND (power), K2 I/O31 D7 (io), K3 I/O28 D4 (io), K4 I/O25 D1 (io), K5 GND (power), K6 GND (power), K7 I/O33 E1 (io), K8 I/O36 E4 (io), K9 I/O39 E7 (io), K10 GND (power)

## M4A3-128/64-7VC
designator U?
High-Performance EE CMOS In-System Programmable Logic
footprint TQFP100_N (Thin QFP, 100-Leads, Body 14x14mm, Pitch 0.5mm, IPC Medium Density)
footprint TQFP100_L (Thin QFP, 100-Leads, Body 14x14mm, Pitch 0.5mm, IPC High Density)
footprint TQFP100_M (Thin QFP, 100-Leads, Body 14x14mm, Pitch 0.5mm, IPC Low Density)
3D model M4A3-TQFP100 (100-Pin Thin Quad Flat Pack (TQFP100))
pins: 1 GND (power), 2 TDI (in), 3 I/O8 B7 (io), 4 I/O9 B6 (io), 5 I/O10 B5 (io), 6 I/O11 B4 (io), 7 I/O12 B3 (io), 8 I/O13 B2 (io), 9 I/O14 B1 (io), 10 I/O15 B0 (io), 11 I0/CLK0 (in), 12 VCC (power), 13 GND (power), 14 I1/CLK1 (in), 15 I/O16 C0 (io), 16 I/O17 C1 (io), 17 I/O18 C2 (io), 18 I/O19 C3 (io), 19 I/O20 C4 (io), 20 I/O21 C5 (io), 21 I/O22 C6 (io), 22 I/O23 C7 (io), 23 TMS (in), 24 TCK (in), 25 GND (power), 26 GND (power), 27 GND (power), 28 I/O24 D7 (io), 29 I/O25 D6 (io), 30 I/O26 D5 (io), 31 I/O27 D4 (io), 32 I/O28 D3 (io), 33 I/O29 D2 (io), 34 I/O30 D1 (io), 35 I/O31 D0 (io), 36 I2 (in), 37 VCC (power), 38 GND (power), 39 GND (power), 40 VCC (power), 41 I/O32 E0 (io), 42 I/O33 E1 (io), 43 I/O34 E2 (io), 44 I/O35 E3 (io), 45 I/O36 E4 (io), 46 I/O37 E5 (io), 47 I/O38 E6 (io), 48 I/O39 E7 (io), 49 GND (power), 50 GND (power), 51 GND (power), 52 ~{ENABLE} (in), 53 I/O40 F7 (io), 54 I/O41 F6 (io), 55 I/O42 F5 (io), 56 I/O43 F4 (io), 57 I/O44 F3 (io), 58 I/O45 F2 (io), 59 I/O46 F1 (io), 60 I/O47 F0 (io), 61 I3/CLK2 (in), 62 VCC (power), 63 GND (power), 64 I4/CLK3 (in), 65 I/O48 G0 (io), 66 I/O49 G1 (io), 67 I/O50 G2 (io), 68 I/O51 G3 (io), 69 I/O52 G4 (io), 70 I/O53 G5 (io), 71 I/O54 G6 (io), 72 I/O55 G7 (io), 73 ~{TRST} (in), 74 TDO (out), 75 GND (power), 76 GND (power), 77 GND (power), 78 I/O56 H7 (io), 79 I/O57 H6 (io), 80 I/O58 H5 (io), 81 I/O59 H4 (io), 82 I/O60 H3 (io), 83 I/O61 H2 (io), 84 I/O62 H1 (io), 85 I/O63 H0 (io), 86 I5 (in), 87 VCC (power), 88 GND (power), 89 GND (power), 90 VCC (power), 91 I/O0 A0 (io), 92 I/O1 A1 (io), 93 I/O2 A2 (io), 94 I/O3 A3 (io), 95 I/O4 A4 (io), 96 I/O5 A5 (io), 97 I/O6 A6 (io), 98 I/O7 A7 (io), 99 GND (power), 100 GND (power)

## M4A3-128/64-7VI
designator U?
High-Performance EE CMOS In-System Programmable Logic
footprint TQFP100_N (Thin QFP, 100-Leads, Body 14x14mm, Pitch 0.5mm, IPC Medium Density)
footprint TQFP100_L (Thin QFP, 100-Leads, Body 14x14mm, Pitch 0.5mm, IPC High Density)
footprint TQFP100_M (Thin QFP, 100-Leads, Body 14x14mm, Pitch 0.5mm, IPC Low Density)
3D model M4A3-TQFP100 (100-Pin Thin Quad Flat Pack (TQFP100))
pins: 1 GND (power), 2 TDI (in), 3 I/O8 B7 (io), 4 I/O9 B6 (io), 5 I/O10 B5 (io), 6 I/O11 B4 (io), 7 I/O12 B3 (io), 8 I/O13 B2 (io), 9 I/O14 B1 (io), 10 I/O15 B0 (io), 11 I0/CLK0 (in), 12 VCC (power), 13 GND (power), 14 I1/CLK1 (in), 15 I/O16 C0 (io), 16 I/O17 C1 (io), 17 I/O18 C2 (io), 18 I/O19 C3 (io), 19 I/O20 C4 (io), 20 I/O21 C5 (io), 21 I/O22 C6 (io), 22 I/O23 C7 (io), 23 TMS (in), 24 TCK (in), 25 GND (power), 26 GND (power), 27 GND (power), 28 I/O24 D7 (io), 29 I/O25 D6 (io), 30 I/O26 D5 (io), 31 I/O27 D4 (io), 32 I/O28 D3 (io), 33 I/O29 D2 (io), 34 I/O30 D1 (io), 35 I/O31 D0 (io), 36 I2 (in), 37 VCC (power), 38 GND (power), 39 GND (power), 40 VCC (power), 41 I/O32 E0 (io), 42 I/O33 E1 (io), 43 I/O34 E2 (io), 44 I/O35 E3 (io), 45 I/O36 E4 (io), 46 I/O37 E5 (io), 47 I/O38 E6 (io), 48 I/O39 E7 (io), 49 GND (power), 50 GND (power), 51 GND (power), 52 ~{ENABLE} (in), 53 I/O40 F7 (io), 54 I/O41 F6 (io), 55 I/O42 F5 (io), 56 I/O43 F4 (io), 57 I/O44 F3 (io), 58 I/O45 F2 (io), 59 I/O46 F1 (io), 60 I/O47 F0 (io), 61 I3/CLK2 (in), 62 VCC (power), 63 GND (power), 64 I4/CLK3 (in), 65 I/O48 G0 (io), 66 I/O49 G1 (io), 67 I/O50 G2 (io), 68 I/O51 G3 (io), 69 I/O52 G4 (io), 70 I/O53 G5 (io), 71 I/O54 G6 (io), 72 I/O55 G7 (io), 73 ~{TRST} (in), 74 TDO (out), 75 GND (power), 76 GND (power), 77 GND (power), 78 I/O56 H7 (io), 79 I/O57 H6 (io), 80 I/O58 H5 (io), 81 I/O59 H4 (io), 82 I/O60 H3 (io), 83 I/O61 H2 (io), 84 I/O62 H1 (io), 85 I/O63 H0 (io), 86 I5 (in), 87 VCC (power), 88 GND (power), 89 GND (power), 90 VCC (power), 91 I/O0 A0 (io), 92 I/O1 A1 (io), 93 I/O2 A2 (io), 94 I/O3 A3 (io), 95 I/O4 A4 (io), 96 I/O5 A5 (io), 97 I/O6 A6 (io), 98 I/O7 A7 (io), 99 GND (power), 100 GND (power)

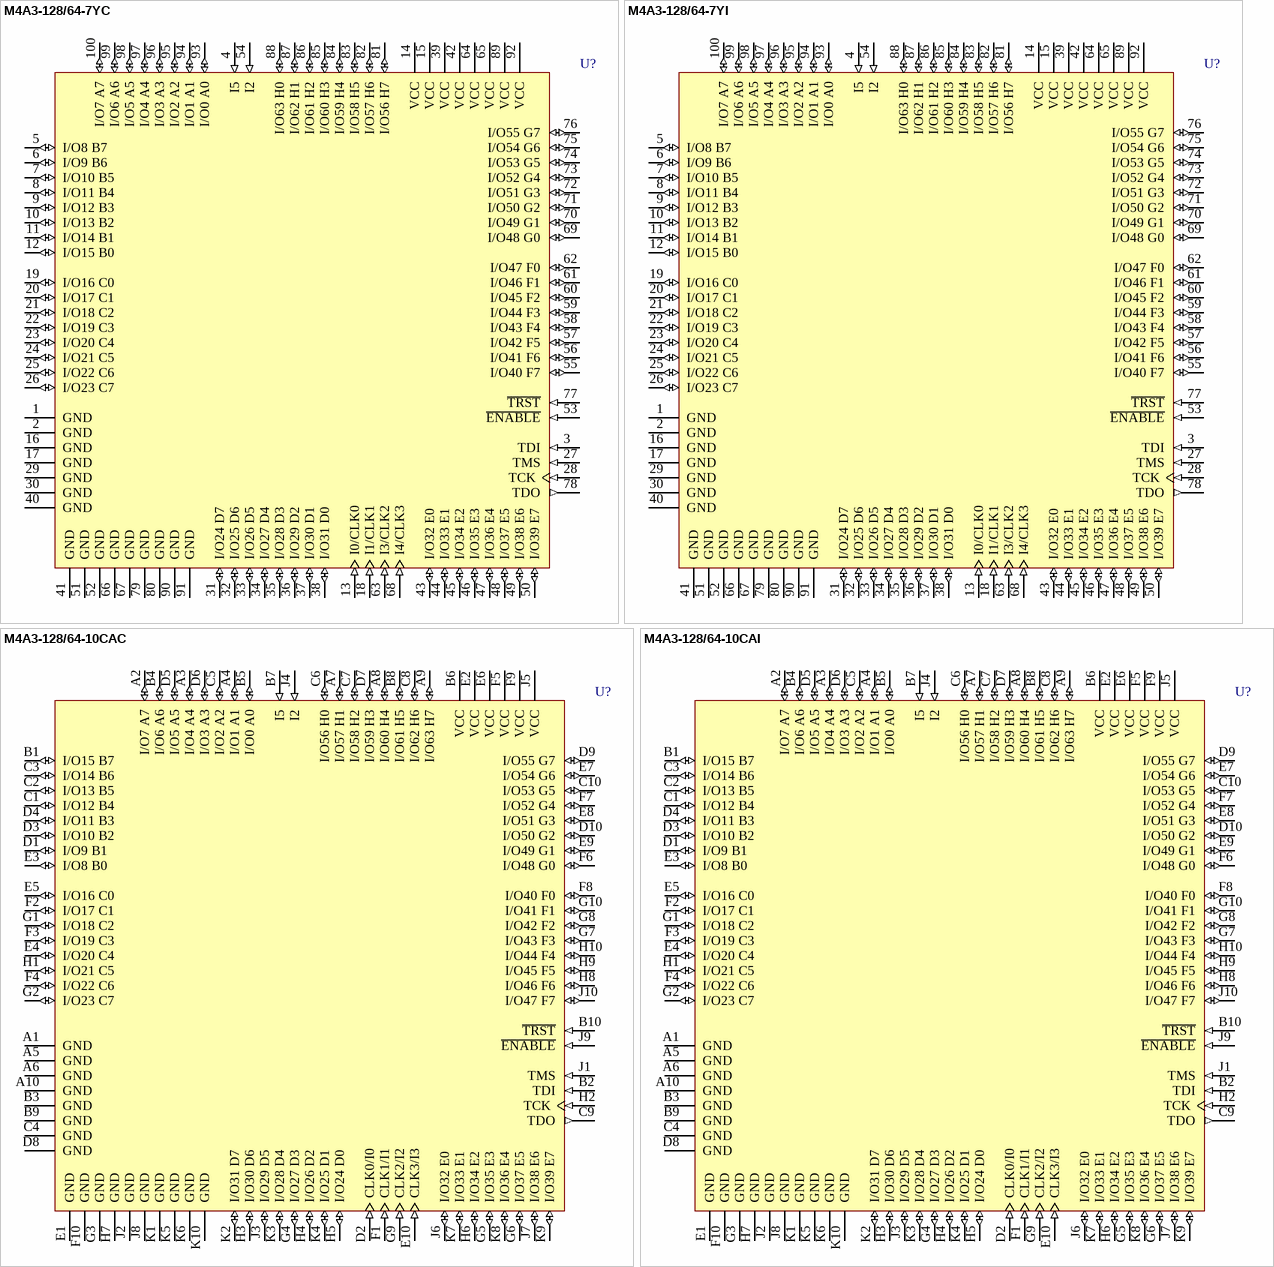
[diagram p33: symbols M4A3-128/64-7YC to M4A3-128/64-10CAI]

## M4A3-128/64-7YC
designator U?
High-Performance EE CMOS In-System Programmable Logic
footprint PQFP100_N (QFP, 100-Leads, Body 20x14mm, Pitch 0.65mm, IPC Medium Density)
footprint PQFP100_L (QFP, 100-Leads, Body 20x14mm, Pitch 0.65mm, IPC High Density)
footprint PQFP100_M (QFP, 100-Leads, Body 20x14mm, Pitch 0.65mm, IPC Low Density)
3D model PQFP-100 (100-Pin Quad Flat Pack Rectangular 0.65 mm Pitch)
pins: 1 GND (power), 2 GND (power), 3 TDI (in), 4 I5 (in), 5 I/O8 B7 (io), 6 I/O9 B6 (io), 7 I/O10 B5 (io), 8 I/O11 B4 (io), 9 I/O12 B3 (io), 10 I/O13 B2 (io), 11 I/O14 B1 (io), 12 I/O15 B0 (io), 13 I0/CLK0 (in), 14 VCC (power), 15 VCC (power), 16 GND (power), 17 GND (power), 18 I1/CLK1 (in), 19 I/O16 C0 (io), 20 I/O17 C1 (io), 21 I/O18 C2 (io), 22 I/O19 C3 (io), 23 I/O20 C4 (io), 24 I/O21 C5 (io), 25 I/O22 C6 (io), 26 I/O23 C7 (io), 27 TMS (in), 28 TCK (in), 29 GND (power), 30 GND (power), 31 I/O24 D7 (io), 32 I/O25 D6 (io), 33 I/O26 D5 (io), 34 I/O27 D4 (io), 35 I/O28 D3 (io), 36 I/O29 D2 (io), 37 I/O30 D1 (io), 38 I/O31 D0 (io), 39 VCC (power), 40 GND (power), 41 GND (power), 42 VCC (power), 43 I/O32 E0 (io), 44 I/O33 E1 (io), 45 I/O34 E2 (io), 46 I/O35 E3 (io), 47 I/O36 E4 (io), 48 I/O37 E5 (io), 49 I/O38 E6 (io), 50 I/O39 E7 (io), 51 GND (power), 52 GND (power), 53 ~{ENABLE} (in), 54 I2 (in), 55 I/O40 F7 (io), 56 I/O41 F6 (io), 57 I/O42 F5 (io), 58 I/O43 F4 (io), 59 I/O44 F3 (io), 60 I/O45 F2 (io), 61 I/O46 F1 (io), 62 I/O47 F0 (io), 63 I3/CLK2 (in), 64 VCC (power), 65 VCC (power), 66 GND (power), 67 GND (power), 68 I4/CLK3 (in), 69 I/O48 G0 (io), 70 I/O49 G1 (io), 71 I/O50 G2 (io), 72 I/O51 G3 (io), 73 I/O52 G4 (io), 74 I/O53 G5 (io), 75 I/O54 G6 (io), 76 I/O55 G7 (io), 77 ~{TRST} (in), 78 TDO (out), 79 GND (power), 80 GND (power), 81 I/O56 H7 (io), 82 I/O57 H6 (io), 83 I/O58 H5 (io), 84 I/O59 H4 (io), 85 I/O60 H3 (io), 86 I/O61 H2 (io), 87 I/O62 H1 (io), 88 I/O63 H0 (io), 89 VCC (power), 90 GND (power), 91 GND (power), 92 VCC (power), 93 I/O0 A0 (io), 94 I/O1 A1 (io), 95 I/O2 A2 (io), 96 I/O3 A3 (io), 97 I/O4 A4 (io), 98 I/O5 A5 (io), 99 I/O6 A6 (io), 100 I/O7 A7 (io)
